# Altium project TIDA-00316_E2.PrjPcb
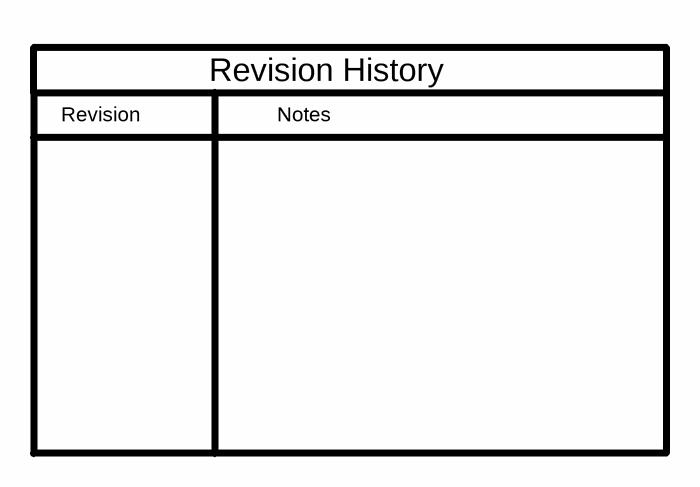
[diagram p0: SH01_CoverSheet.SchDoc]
CopyrightYear: 2015; EVM_Orderable: N/A; PCB_Layout: Avinash N; PCB_Rev: E2; PRJ_Customer: Public Release; PRJ_Engineer: Sanjay Pithadia; PRJ_Number: TIDA-00316; PRJ_Title: Motor Current Measurement using Hall Sensors; SCH_Rev: E2; TechSupport: http://www.ti.com/support; TID: ChangeMe!
6 sheets, 219 parts. Net scope: flat (ports and power ports of the same name join across sheets).
Board file: TIDA-00316_E2.PcbDoc
Sheets:
  SH01_CoverSheet.SchDoc
  SH02_Power_supply.SchDoc
  SH03_Single_ended_SC_to_ADC.SchDoc
  SH04_Fully_differential_ended_SC_to_ADC.SchDoc
  SH05_180_pin_connector_interface.SchDoc
  SH06_Hardware.SchDoc

## Sheet SH01_CoverSheet.SchDoc: Block Diagram
size 431 x 279 mm; Date: Not shown in title block; ApprovedBy: Not shown in title block; CheckedBy: Not shown in title block; Author: Not shown in title block; CompanyName: Not shown in title block; DrawnBy: Sanjay Pithadia; Engineer: Sanjay Pithadia; Organization: Not shown in title block; Address1: Not shown in title block; Address2: Not shown in title block; Address3: Not shown in title block; Address4: Not shown in title block; DocumentNumber: 1; Revision: Use project parameter SCH_Rev; SheetNumber: 1; SheetTotal: 6; PageSetup: Record=PageOptions|CenterHorizontal=True|CenterVertical=True|PrintScale=1.00|XCorrection=1.00|YCorrection=1.00|PrintKind=0|BorderSize=5000000|LeftOffset=0|BottomOffset=0|Orientation=2|PaperLength=1000|PaperWidth=1000|Scale=100|PaperSource=15|PrintQuality=600|MediaType=1|DitherType=10|PaperKind=Letter|PrintScaleMode=1

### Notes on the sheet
- Revision
- Notes
- Revision History

## Sheet SH02_Power_supply.SchDoc: Power Supply
size 431 x 279 mm; Date: Not shown in title block; ApprovedBy: Not shown in title block; CheckedBy: Not shown in title block; Author: Not shown in title block; CompanyName: Not shown in title block; DrawnBy: Sanjay Pithadia; Engineer: Sanjay Pithadia; Organization: Not shown in title block; Address1: Not shown in title block; Address2: Not shown in title block; Address3: Not shown in title block; Address4: Not shown in title block; DocumentNumber: 1; Revision: Use project parameter SCH_Rev; SheetNumber: 2; SheetTotal: 6; PageSetup: Record=PageOptions|CenterHorizontal=True|CenterVertical=True|PrintScale=1.00|XCorrection=1.00|YCorrection=1.00|PrintKind=0|BorderSize=5000000|LeftOffset=0|BottomOffset=0|Orientation=2|PaperLength=1000|PaperWidth=1000|Scale=100|PaperSource=15|PrintQuality=600|MediaType=1|DitherType=10|PaperKind=Letter|PrintScaleMode=1
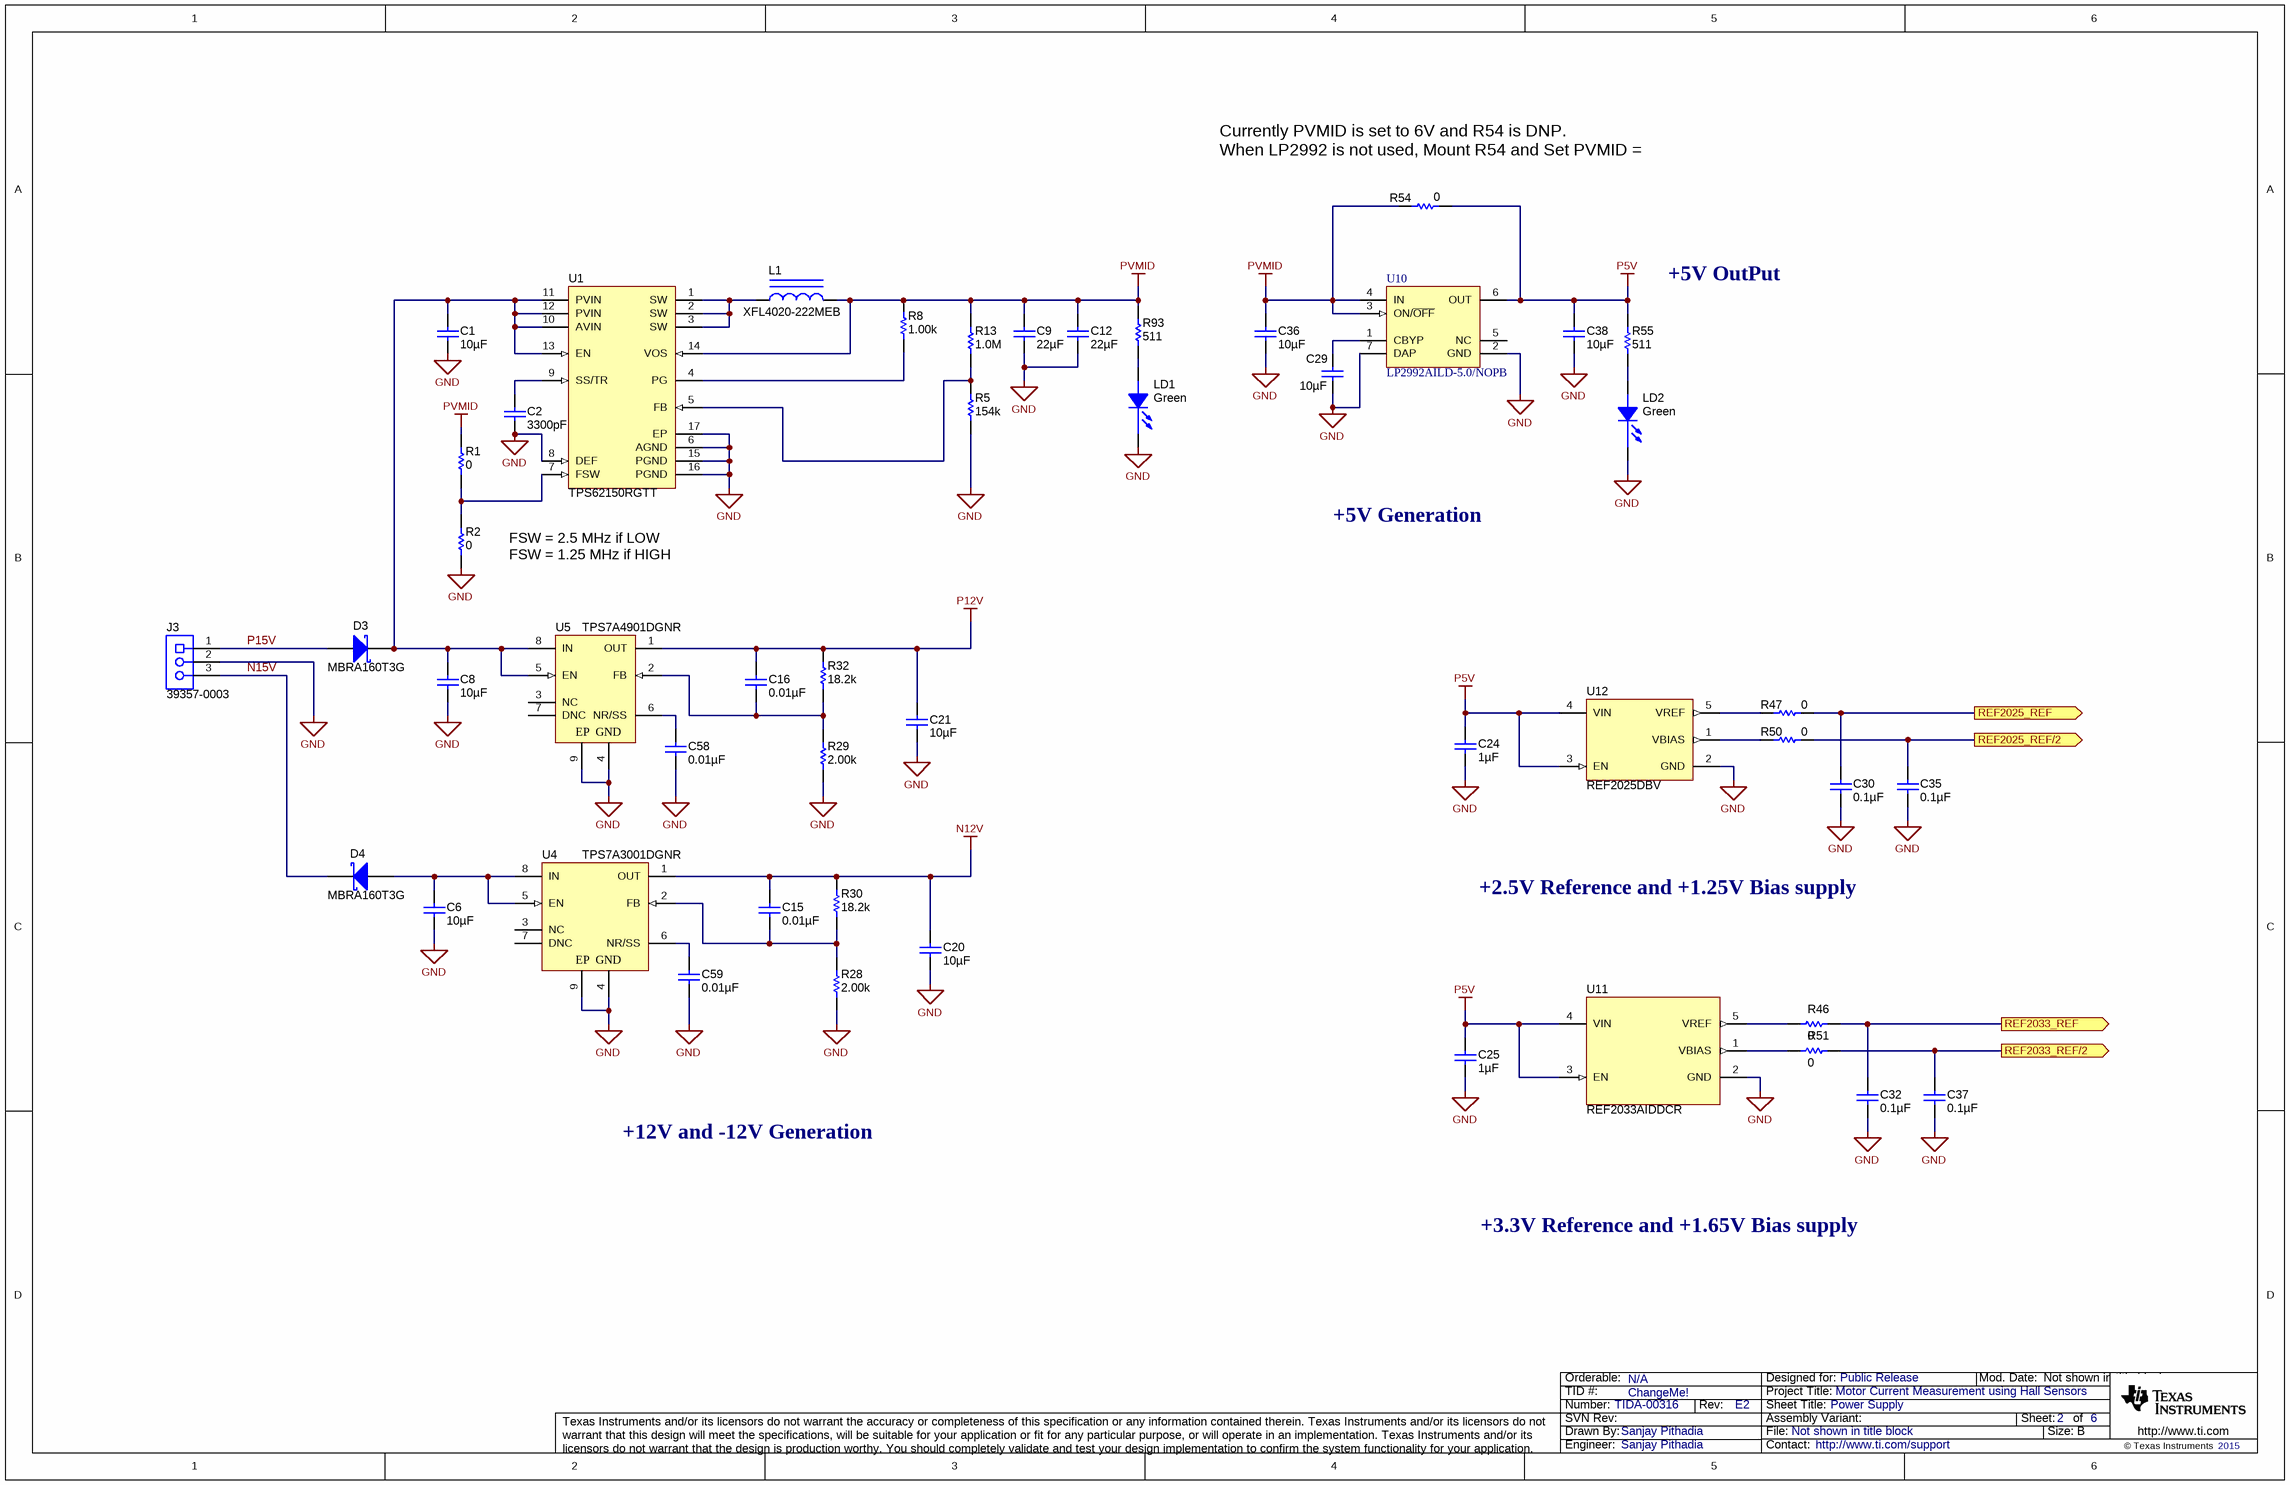
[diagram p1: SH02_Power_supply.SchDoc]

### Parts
C1  ValueDisplayed: 10µF  [1210]  (hidden comment: C3216X7R1V106M160AC)
C2  ValueDisplayed: 3300pF  [0805_HV]  (hidden comment: C0805C332K5RACTU)
C6  ValueDisplayed: 10µF  [0805_140]  (hidden comment: GRM21BR61E106KA73L)
C8  ValueDisplayed: 10µF  [0805_140]  (hidden comment: GRM21BR61E106KA73L)
C9  ValueDisplayed: 22µF  [0805_HV]  (hidden comment: C2012X5R1C226K125AC)
C12  ValueDisplayed: 22µF  [0805_HV]  (hidden comment: C2012X5R1C226K125AC)
C15  ValueDisplayed: 0.01µF  [0603]  (hidden comment: C1608C0G1E103J)
C16  ValueDisplayed: 0.01µF  [0603]  (hidden comment: C1608C0G1E103J)
C20  ValueDisplayed: 10µF  [0805_140]  (hidden comment: GRM21BR61E106KA73L)
C21  ValueDisplayed: 10µF  [0805_140]  (hidden comment: GRM21BR61E106KA73L)
C24  ValueDisplayed: 1µF  [0805_HV]  (hidden comment: C0805C105K8RACTU)
C25  ValueDisplayed: 1µF  [0805_HV]  (hidden comment: C0805C105K8RACTU)
C29  ValueDisplayed: 10µF  [0805_140]  (hidden comment: GRM21BR61E106KA73L)
C30  ValueDisplayed: 0.1µF  [0603]  (hidden comment: GRM188R71H104KA93D)
C32  ValueDisplayed: 0.1µF  [0603]  (hidden comment: GRM188R71H104KA93D)
C35  ValueDisplayed: 0.1µF  [0603]  (hidden comment: GRM188R71H104KA93D)
C36  ValueDisplayed: 10µF  [0805_140]  (hidden comment: GRM21BR61E106KA73L)
C37  ValueDisplayed: 0.1µF  [0603]  (hidden comment: GRM188R71H104KA93D)
C38  ValueDisplayed: 10µF  [0805_140]  (hidden comment: GRM21BR61E106KA73L)
C58  ValueDisplayed: 0.01µF  [0603]  (hidden comment: C1608C0G1E103J)
C59  ValueDisplayed: 0.01µF  [0603]  (hidden comment: C1608C0G1E103J)
D3  MBRA160T3G  [SMA]
D4  MBRA160T3G  [SMA]
J3  39357-0003  [Molex_39357-0003]
L1  XFL4020-222MEB  [XFL4020]
LD1  value Green  [LED0603AA]  (hidden comment: LED_LG L29K-G2J1-24-Z)
LD2  value Green  [LED0603AA]  (hidden comment: LED_LG L29K-G2J1-24-Z)
R1  ValueDisplayed: 0  [0603]  (hidden comment: CRCW06030000Z0EA)
R2  ValueDisplayed: 0  [0603]  (hidden comment: CRCW06030000Z0EA)
R5  ValueDisplayed: 154k  [0603]  (hidden comment: CRCW0603154KFKEA)
R8  ValueDisplayed: 1.00k  [0603]  (hidden comment: CRCW06031K00FKEA)
R13  ValueDisplayed: 1.0M  [0603]  (hidden comment: CRCW06031M00JNEA)
R28  ValueDisplayed: 2.00k  [0603]  (hidden comment: CRCW06032K00FKEA)
R29  ValueDisplayed: 2.00k  [0603]  (hidden comment: CRCW06032K00FKEA)
R30  ValueDisplayed: 18.2k  [0603]  (hidden comment: CRCW060318K2FKEA)
R32  ValueDisplayed: 18.2k  [0603]  (hidden comment: CRCW060318K2FKEA)
R46  value 0  [0603]  (hidden comment: CRCW06030000Z0EA)
R47  value 0  [0603]  (hidden comment: CRCW06030000Z0EA)
R50  value 0  [0603]  (hidden comment: CRCW06030000Z0EA)
R51  value 0  [0603]  (hidden comment: CRCW06030000Z0EA)
R54  value 0  [0603]  (hidden comment: CRCW06030000Z0EA)
R55  ValueDisplayed: 511  [0603]  (hidden comment: RT0603DRE07511RL)
R93  ValueDisplayed: 511  [0603]  (hidden comment: RT0603DRE07511RL)
U1  TPS62150RGTT  [RGT0016C]
U4  TPS7A3001DGNR  [DGN0008D_N]
U5  TPS7A4901DGNR  [DGN0008D_N]
U10  LP2992AILD-5.0/NOPB  [LDE06A]
U11  REF2033AIDDCR  [DDC0005A_N]
U12  REF2025DBV  [DBV0005A_N]

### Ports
REF2025_REF (out), REF2025_REF/2 (out), REF2033_REF (out), REF2033_REF/2 (out)

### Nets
GND: C1.2 C2.2 C6.2 C8.2 C9.2 C12.2 C20.2 C21.2 C24.2 C25.2 C29.2 C30.2 C32.2 C35.2 C36.2 C37.2 C38.2 C58.2 C59.2 J3.2 LD1.1(C) LD2.1(C) R2.1 R5.1 R28.1 R29.1 U1.6(AGND) U1.8(DEF) U1.15(PGND) U1.16(PGND) U1.17(EP) U4.4(GND) U4.9(EP) U5.4(GND) U5.9(EP) U10.2(GND) U10.7(DAP) U11.2(GND) U12.2(GND)
N12V: C15.1 C20.1 R30.2 U4.1(OUT)
P5V: C24.1 C25.1 C38.1 R54.1 R55.2 U10.6(OUT) U11.3(EN) U11.4(VIN) U12.3(EN) U12.4(VIN)
P12V: C16.1 C21.1 R32.2 U5.1(OUT)
PVMID: C9.1 C12.1 C36.1 L1.2 R1.2 R8.2 R13.2 R54.2 R93.2 U1.14(VOS) U10.3(ON/~{OFF}) U10.4(IN)
N15V: D4.1(K) J3.3
P15V: D3.2(A) J3.1
REF2025_REF: C30.1 R47.1 ; port REF2025_REF
REF2025_REF/2: C35.1 R50.1 ; port REF2025_REF/2
REF2033_REF: C32.1 R46.1 ; port REF2033_REF
REF2033_REF/2: C37.1 R51.1 ; port REF2033_REF/2
NetC1_1: C1.1 C8.1 D3.1(K) U1.10(AVIN) U1.11(PVIN) U1.12(PVIN) U1.13(EN) U5.5(EN) U5.8(IN)
NetC2_1: C2.1 U1.9(SS/TR)
NetC6_1: C6.1 D4.2(A) U4.5(EN) U4.8(IN)
NetC15_2: C15.2 R28.2 R30.1 U4.2(FB)
NetC16_2: C16.2 R29.2 R32.1 U5.2(FB)
NetC29_1: C29.1 U10.1(CBYP)
NetC58_1: C58.1 U5.6(NR/SS)
NetC59_1: C59.1 U4.6(NR/SS)
NetL1_1: L1.1 U1.1(SW) U1.2(SW) U1.3(SW)
NetLD1_2: LD1.2(A) R93.1
NetLD2_2: LD2.2(A) R55.1
NetR1_1: R1.1 R2.2 U1.7(FSW)
NetR5_2: R5.2 R13.1 U1.5(FB)
NetR8_1: R8.1 U1.4(PG)
NetR46_2: R46.2 U11.5(VREF)
NetR47_2: R47.2 U12.5(VREF)
NetR50_2: R50.2 U12.1(VBIAS)
NetR51_2: R51.2 U11.1(VBIAS)

Not connected (* = marked no-connect by the designer): U4 3(NC) 7(DNC); U5 3(NC) 7(DNC); U10 5(NC)

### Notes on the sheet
- (near R54) Currently PVMID is set to 6V and R54 is DNP.
  When LP2992 is not used, Mount R54 and Set PVMID = 5V
- +5V OutPut
- FSW = 2.5 MHz if LOW
  FSW = 1.25 MHz if HIGH
- +5V Generation
- +2.5V Reference and +1.25V Bias supply
- +12V and -12V Generation
- +3.3V Reference and +1.65V Bias supply

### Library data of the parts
C1 = C3216X7R1V106M160AC: CAP, CERM, 10 µF, 35 V, +/- 20%, X7R, 1206_190; Manufacturer: TDK; Polarized: N; CompType: Capacitor; Value: 10uF; U/M: EA; Cap_F: 0.00001; Tolerance_%: 20; Value1: Unknown; VDC_V: 35; Value2: 35V; TaMin_C: -55; TaMax_C: 125; Cap_Case: 1206
C2 = C0805C332K5RACTU: CAP, CERM, 3300 pF, 50 V, +/- 10%, X7R, 0805; Manufacturer: Kemet; Polarized: N; CompType: Capacitor; Value: 3300pF; U/M: EA; Cap_F: 0.0000000033; Tolerance_%: 10; ESR_ohm: 0.332; Value1: 0.332 ohm; VDC_V: 50; Value2: 50V; IRMS_A: 0.319; TaMin_C: -55; TaMax_C: 125; Cap_Case: 0805
C6 C8 C20 C21 C29 C36 C38 = GRM21BR61E106KA73L: CAP, CERM, 10 µF, 25 V, +/- 10%, X5R, 0805_140; Manufacturer: MuRata; Polarized: N; CompType: Capacitor; Value: 10uF; U/M: EA; Cap_F: 0.00001; Tolerance_%: 10; Value1: Unknown; VDC_V: 25; Value2: 25V; TaMin_C: -55; TaMax_C: 85; Cap_Case: 0805
C9 C12 = C2012X5R1C226K125AC: CAP, CERM, 22 µF, 16 V, +/- 10%, X5R, 0805; Manufacturer: TDK; Polarized: N; CompType: Capacitor; Value: 22uF; U/M: EA; Cap_F: 0.000022; Tolerance_%: 10; Value1: Unknown; VDC_V: 16; Value2: 16V; TaMin_C: -55; TaMax_C: 85; Cap_Case: 0805
C15 C16 C58 C59 = C1608C0G1E103J: CAP, CERM, 0.01 µF, 25 V, +/- 5%, C0G/NP0, 0603; Manufacturer: TDK; Polarized: N; CompType: Capacitor; Value: 0.01uF; U/M: EA; Cap_F: 0.00000001; Tolerance_%: 5; Value1: Unknown; VDC_V: 25; Value2: 25V; TaMin_C: -55; TaMax_C: 125
C24 C25 = C0805C105K8RACTU: CAP, CERM, 1uF, 10V, +/-10%, X7R, 0805; Manufacturer: Kemet; Polarized: N; CompType: Capacitor; U/M: EA; Cap_F: 0.000001; Tolerance_%: 10; ESR_Ohm: 0.015; Value1: 0.015 ohm; IRMS_A: 8.19; TaMin_C: -55; TaMax_C: 125; Cap_Case: 0805
C30 C32 C35 C37 = GRM188R71H104KA93D: CAP, CERM, 0.1 µF, 50 V, +/- 10%, X7R, 0603; Manufacturer: MuRata; Polarized: N; CompType: Capacitor; Value: 0.1uF; U/M: EA; Cap_F: 0.0000001; Tolerance_%: 10; Value1: Unknown; VDC_V: 50; Value2: 50V; TaMin_C: -55; TaMax_C: 125
D3 D4 = MBRA160T3G: Diode, Schottky, 60V, 1A, SMA; Manufacturer: ON Semiconductor; U/M: EA; Vf_V: 0.51; Value2: 0.51V; Io_A: 1; Vr_V: 60; TJmax_C: 150; RJC_CperW: 35
J3 = 39357-0003: Terminal Block, 3.5 mm, 3x1, Tin, TH; Manufacturer: Molex; SymbolCreator: a0412235; U/M: EA
L1 = XFL4020-222MEB: Inductor, Shielded, Composite, 2.2 µH, 3.7 A, 0.02 ohm, SMD; Manufacturer: Coilcraft; Value: 2.2uH; Ind_H: 2.2E-6; ValueDisplayed: 2.2µH; Imax_A: 3.7; Irms: 8A @ 40C rise; Isat: 3.7A @ 30% inductance drop; DCR_ohm: 0.02; Value2: 3.7A
LD1 LD2 = LED_LG L29K-G2J1-24-Z: LED SmartLED Green 570NM; Manufacturer: OSRAM; SymbolCreator: x0120606
R1 R2 = CRCW06030000Z0EA: RES, 0, 5%, 0.1 W, 0603; Manufacturer: Vishay-Dale; CompType: Resistor; Value: 0; Value_Code: 0000; Tolerance_%: 5; Power_W: 0.1; Value2: 0.1W; VDC_V: 75; TempCo: 200 ppm/C; EIA_Code: E24; U/M: EA
R5 = CRCW0603154KFKEA: RES, 154 k, 1%, 0.1 W, 0603; Manufacturer: Vishay-Dale; CompType: Resistor; Value: 154k; Res_ohm: 154000; Tolerance_%: 1; Power_W: 0.1; Value2: 0.1W; VDC_V: 75; TempCo: 100 ppm/C; EIA_Code: E96; U/M: EA
R8 = CRCW06031K00FKEA: RES, 1.00 k, 1%, 0.1 W, 0603; Manufacturer: Vishay-Dale; CompType: Resistor; Value: 1.00k; Res_ohm: 1000; Value_Code: 1k00; Tolerance_%: 1; Power_W: 0.1; Value2: 0.1W; VDC_V: 75; TempCo: 100 ppm/C; EIA_Code: E96; U/M: EA
R13 = CRCW06031M00JNEA: RES, 1.0 M, 5%, 0.1 W, 0603; Manufacturer: Vishay-Dale; CompType: Resistor; Value: 1.0Meg; Res_ohm: 1000000; Value_Code: 1M00; Tolerance_%: 5; Power_W: 0.1; Value2: 0.1W; VDC_V: 75; TempCo: 200 ppm/C; EIA_Code: E24; U/M: EA
R28 R29 = CRCW06032K00FKEA: RES, 2.00 k, 1%, 0.1 W, 0603; Manufacturer: Vishay-Dale; CompType: Resistor; Value: 2.00k; Res_ohm: 2000; Value_Code: 2k00; Tolerance_%: 1; Power_W: 0.1; Value2: 0.1W; VDC_V: 75; TempCo: 100 ppm/C; EIA_Code: E96; U/M: EA
R30 R32 = CRCW060318K2FKEA: RES, 18.2 k, 1%, 0.1 W, 0603; Manufacturer: Vishay-Dale; CompType: Resistor; Value: 18.2k; Res_ohm: 18200; Value_Code: 18k2; Tolerance_%: 1; Power_W: 0.1; Value2: 0.1W; VDC_V: 75; TempCo: 100 ppm/C; EIA_Code: E96; U/M: EA
R46 R47 R50 R51 R54 = CRCW06030000Z0EA: RES, 0 ohm, 5%, 0.1W, 0603; Manufacturer: Vishay-Dale; CompType: Resistor; Value_Code: 0000; Tolerance_%: 5; Power_W: 0.1; VDC_V: 75; TempCo: 200 ppm/C; EIA_Code: E24; U/M: EA
R55 R93 = RT0603DRE07511RL: RES, 511, 0.5%, 0.1 W, 0603; Manufacturer: Yageo America; CompType: Resistor; Value: 511; Value_Code: 511R; Tolerance_%: 0.5; Power_W: 0.1; Value2: 0.1W; VDC_V: 75; TempCo: 50 ppm/C; EIA_Code: E192; U/M: EA
U1 = TPS62150RGTT: Buck Step Down Regulator with 3 to 17 V Input and 0.9 to 6 V Output, -40 to 85 degC, 16-Pin QFN (RGT), Green (RoHS & no Sb/Br); Manufacturer: Texas Instruments; Alternate Manufacturer: None; Alternate PartNumber: Equivalent; Duty Cycle(Max)(%): 100; Iout(Max)(A): 1; Iq(Typ)(mA): 0.017; Rating: Catalog; SubFamily: Step-Down Regulator; Switch Current Limit(Typ)(A): 1.7; Synchronous Rectification: TRUE; Vin(Max)(V): 17; Vin(Min)(V): 3; Vout(Max)(V): 6; Vout(Min)(V): 0.9
U4 = TPS7A3001DGNR: Single Output High PSRR LDO, 200 mA, Adjustable -1.18 to -33 V Output, -3 to -36 V Input, with Ultra-Low Noise, 8-pin MSOP (DGN), -40 to 125 degC, Green (RoHS & no Sb/Br); Manufacturer: Texas Instruments; Alternate Manufacturer: None; Alternate PartNumber: Equivalent; Accuracy(%): 1.5; Iout(Max)(A): 0.2; Iq(Typ)(mA): 0.05; SubFamily: Single Channel LDO; Vdo(Typ)(mV): 216
U5 = TPS7A4901DGNR: Single Output High PSRR LDO, 150 mA, Adjustable 1.2 to 33 V Output, 3 to 36 V Input, with Ultra-Low Noise, 8-pin MSOP (DGN), -40 to 125 degC, Green (RoHS & no Sb/Br); Manufacturer: Texas Instruments; Alternate Manufacturer: None; Alternate PartNumber: Equivalent; Accuracy(%): 1.5; Iout(Max)(A): 0.15; Iq(Typ)(mA): 0.06; Power Good: TRUE; SubFamily: Single Channel LDO; Vdo(Typ)(mV): 260; Vin(Max)(V): 36; Vin(Min)(V): 3; Vout Adj(Max)(V): 33; Vout Adj(Min)(V): 1.2
U10 = LP2992AILD-5.0/NOPB: Micropower 250 mA Low-Noise Ultra Low-Dropout Regulator, 6-pin LLP, Pb-Free; Manufacturer: Texas Instruments; PackageTopMarking: ZXYTT*L015A; PowerWise: N; CompType: LDO IC
U11 = REF2033AIDDCR: Low-Drift, Low-Power, Dual-Output, VREF and VREF / 2 Voltage References, DDC0005A; Alternate PartNumber: REF2033AIDDCT; Manufacturer: Texas Instruments; SymbolCreator: a0799628; CompType: IC; U/M: EA
U12 = REF2025DBV: DUAL OUTPUT VOLTAGE REFERENCE 2.5V, DBV0005A; Alternate Manufacturer: None; Manufacturer: Texas Instruments; SymbolCreator: a0799628; CompType: IC; U/M: EA

## Sheet SH03_Single_ended_SC_to_ADC.SchDoc: Signal Chain - Pseudo Differential
size 431 x 279 mm; Date: Not shown in title block; ApprovedBy: Not shown in title block; CheckedBy: Not shown in title block; Author: Not shown in title block; CompanyName: Not shown in title block; DrawnBy: Sanjay Pithadia; Engineer: Sanjay Pithadia; Organization: Not shown in title block; Address1: Not shown in title block; Address2: Not shown in title block; Address3: Not shown in title block; Address4: Not shown in title block; DocumentNumber: 1; Revision: Use project parameter SCH_Rev; SheetNumber: 3; SheetTotal: 6; PageSetup: Record=PageOptions|CenterHorizontal=True|CenterVertical=True|PrintScale=1.00|XCorrection=1.00|YCorrection=1.00|PrintKind=0|BorderSize=5000000|LeftOffset=0|BottomOffset=0|Orientation=2|PaperLength=1000|PaperWidth=1000|Scale=100|PaperSource=15|PrintQuality=600|MediaType=1|DitherType=10|PaperKind=Letter|PrintScaleMode=1
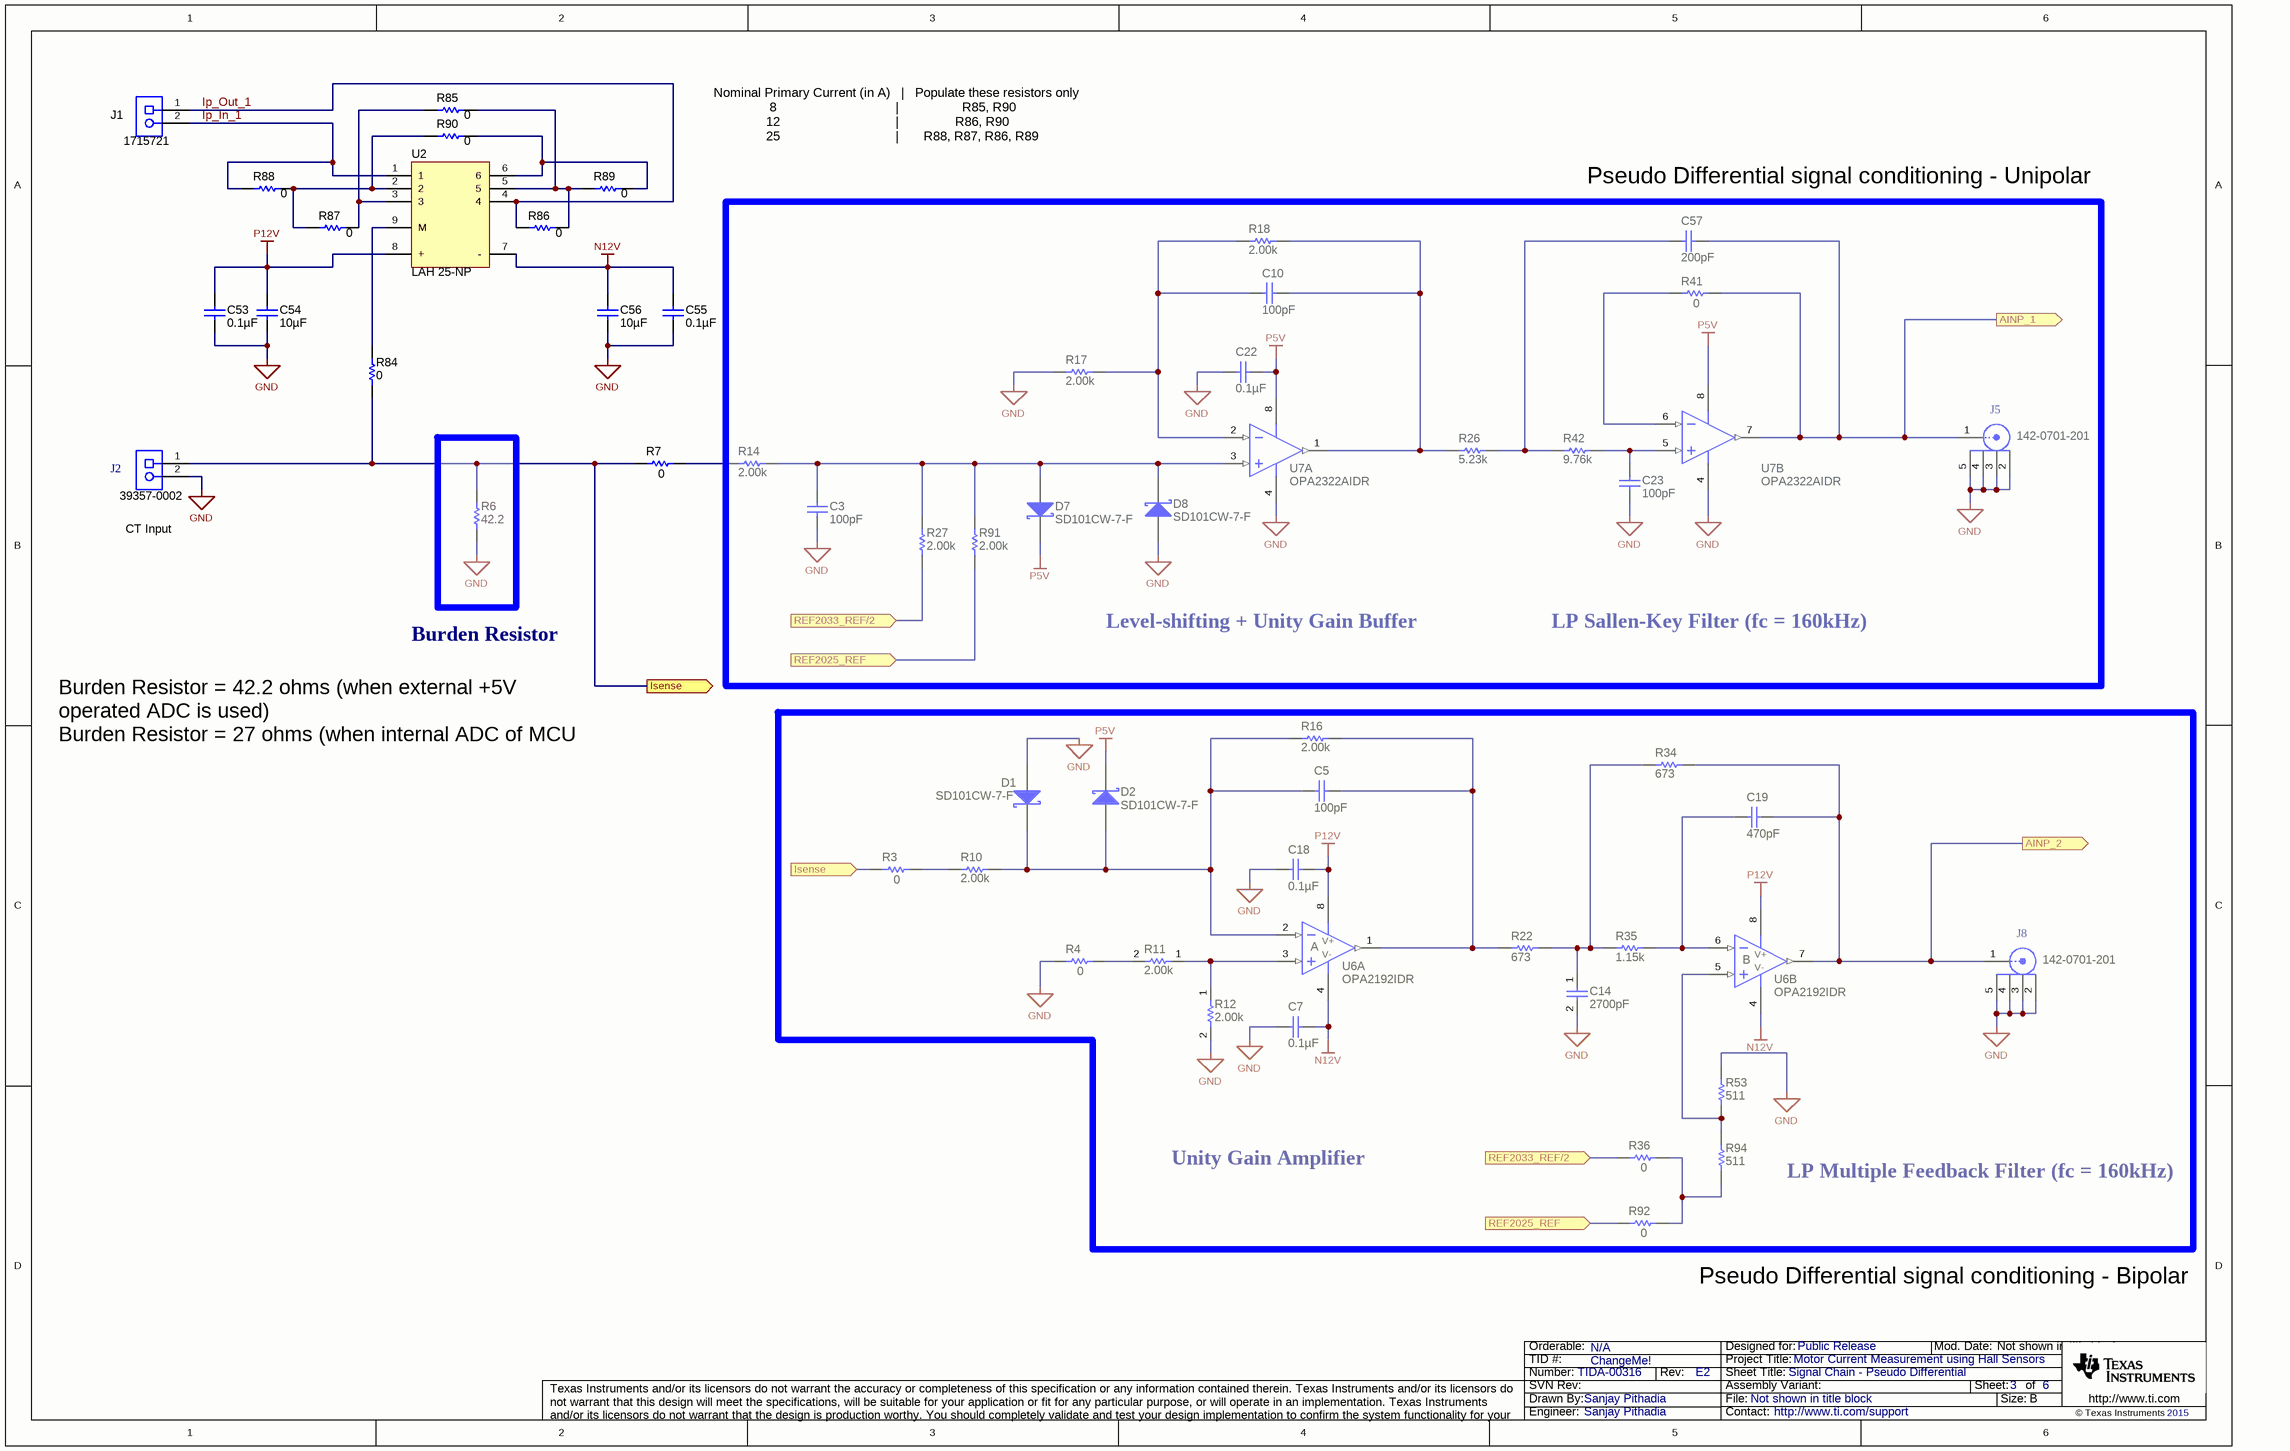
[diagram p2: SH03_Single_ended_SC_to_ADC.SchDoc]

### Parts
C3  ValueDisplayed: 100pF  [0603]  (hidden comment: C1608C0G2A101J)
C5  ValueDisplayed: 100pF  [0603]  (hidden comment: C1608C0G2A101J)
C7  ValueDisplayed: 0.1µF  [0603]  (hidden comment: GRM188R71H104KA93D)
C10  ValueDisplayed: 100pF  [0603]  (hidden comment: C1608C0G2A101J)
C14  ValueDisplayed: 2700pF  [0603]  (hidden comment: C1608C0G1H272J)
C18  ValueDisplayed: 0.1µF  [0603]  (hidden comment: GRM188R71H104KA93D)
C19  ValueDisplayed: 470pF  [0603]  (hidden comment: 06035A471JAT2A)
C22  ValueDisplayed: 0.1µF  [0603]  (hidden comment: GRM188R71H104KA93D)
C23  ValueDisplayed: 100pF  [0603]  (hidden comment: C1608C0G2A101J)
C53  ValueDisplayed: 0.1µF  [0603]  (hidden comment: GRM188R71H104KA93D)
C54  ValueDisplayed: 10µF  [0805_140]  (hidden comment: GRM21BR61E106KA73L)
C55  ValueDisplayed: 0.1µF  [0603]  (hidden comment: GRM188R71H104KA93D)
C56  ValueDisplayed: 10µF  [0805_140]  (hidden comment: GRM21BR61E106KA73L)
C57  ValueDisplayed: 200pF  [0603]  (hidden comment: GRM1885C2A201JA01D)
D1  SD101CW-7-F  [SOD-123]
D2  SD101CW-7-F  [SOD-123]
D7  SD101CW-7-F  [SOD-123]
D8  SD101CW-7-F  [SOD-123]
J1  1715721  [PhoenixContact_1715721]
J2  39357-0002  [Molex_39357-0002]
J5  142-0701-201  [Johnson_142-0701-20x]
J8  142-0701-201  [Johnson_142-0701-20x]
R3  value 0  [0603]  (hidden comment: CRCW06030000Z0EA)
R4  value 0  [0603]  (hidden comment: CRCW06030000Z0EA)
R6  ValueDisplayed: 42.2  [0805_HV]  (hidden comment: CRCW080542R2FKEA)
R7  value 0  [0603]  (hidden comment: CRCW06030000Z0EA)
R10  ValueDisplayed: 2.00k  [0603]  (hidden comment: RC0603FR-072KL)
R11  ValueDisplayed: 2.00k  [0603]  (hidden comment: RC0603FR-072KL)
R12  ValueDisplayed: 2.00k  [0603]  (hidden comment: RC0603FR-072KL)
R14  ValueDisplayed: 2.00k  [0603]  (hidden comment: RC0603FR-072KL)
R16  ValueDisplayed: 2.00k  [0603]  (hidden comment: RC0603FR-072KL)
R17  ValueDisplayed: 2.00k  [0603]  (hidden comment: RC0603FR-072KL)
R18  ValueDisplayed: 2.00k  [0603]  (hidden comment: RC0603FR-072KL)
R22  ValueDisplayed: 673  [0603]  (hidden comment: RT0603BRD07673RL)
R26  ValueDisplayed: 5.23k  [0603]  (hidden comment: CRCW06035K23FKEA)
R27  ValueDisplayed: 2.00k  [0603]  (hidden comment: RC0603FR-072KL)
R34  ValueDisplayed: 673  [0603]  (hidden comment: RT0603BRD07673RL)
R35  ValueDisplayed: 1.15k  [0603]  (hidden comment: CRCW06031K15FKEA)
R36  value 0  [0603]  (hidden comment: CRCW06030000Z0EA)
R41  value 0  [0603]  (hidden comment: CRCW06030000Z0EA)
R42  ValueDisplayed: 9.76k  [0603]  (hidden comment: CRCW06039K76FKEA)
R53  ValueDisplayed: 511  [0603]  (hidden comment: RT0603DRE07511RL)
R84  value 0  [0603]  (hidden comment: CRCW06030000Z0EA)
R85  ValueDisplayed: 0  [1206]  (hidden comment: RC1206JR-070RL)
R86  ValueDisplayed: 0  [1206]  (hidden comment: RC1206JR-070RL)
R87  ValueDisplayed: 0  [1206]  (hidden comment: RC1206JR-070RL)
R88  ValueDisplayed: 0  [1206]  (hidden comment: RC1206JR-070RL)
R89  ValueDisplayed: 0  [1206]  (hidden comment: RC1206JR-070RL)
R90  ValueDisplayed: 0  [1206]  (hidden comment: RC1206JR-070RL)
R91  ValueDisplayed: 2.00k  [0603]  (hidden comment: RC0603FR-072KL)
R92  value 0  [0603]  (hidden comment: CRCW06030000Z0EA)
R94  ValueDisplayed: 511  [0603]  (hidden comment: RT0603DRE07511RL)
U2  LAH 25-NP  [LAH25-NP]
U6  OPA2192IDR  [D0008A_N]  (parts A,B of 2)
U7  OPA2322AIDR  [D0008A_N]  (parts A,B of 2)

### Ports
AINP_1 (out), AINP_2 (out), Isense (in), Isense (out), REF2025_REF (in), REF2033_REF/2 (in)

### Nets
GND: C3.2 C7.2 C14.2 C18.2 C22.2 C23.2 C53.2 C54.2 C55.2 C56.2 D1.2(A) D8.2(A) J2.2 J5.2 J5.3 J5.4 J5.5 J8.2 J8.3 J8.4 J8.5 R4.2 R6.1 R12.2 R17.1 R53.2 U7.4(V-)
N12V: C7.1 C55.1 C56.1 U2.7(-) U6.4(V-)
P5V: C22.1 D2.1(K) D7.1(K) U7.8(V+)
P12V: C18.1 C53.1 C54.1 U2.8(+) U6.8(V+)
AINP_1: C57.1 J5.1 R41.1 U7.7(OUT_B) ; port AINP_1
AINP_2: C19.1 J8.1 R34.2 U6.7(OUT) ; port AINP_2
Ip_In_1: J1.2 R88.1 U2.1
Ip_Out_1: J1.1 R86.1 U2.4
Isense: J2.1 R3.2 R6.2 R7.2 R84.2 ; port Isense
REF2025_REF: R91.1 R92.2 ; port REF2025_REF
REF2033_REF/2: R27.1 R36.2 ; port REF2033_REF/2
NetC3_1: C3.1 D7.2(A) D8.1(K) R14.2 R27.2 R91.2 U7.3(IN_A+)
NetC5_1: C5.1 R16.1 R22.1 U6.1(OUT)
NetC5_2: C5.2 D1.1(K) D2.2(A) R10.2 R16.2 U6.2(IN-)
NetC10_1: C10.1 R18.1 R26.1 U7.1(OUT_A)
NetC10_2: C10.2 R17.2 R18.2 U7.2(IN_A-)
NetC14_1: C14.1 R22.2 R34.1 R35.1
NetC19_2: C19.2 R35.2 U6.6(IN-)
NetC23_1: C23.1 R42.2 U7.5(IN_B+)
NetC57_2: C57.2 R26.2 R42.1
NetR3_1: R3.1 R10.1
NetR4_1: R4.1 R11.2
NetR7_1: R7.1 R14.1
NetR11_1: R11.1 R12.1 U6.3(IN+)
NetR36_1: R36.1 R92.1 R94.1
NetR41_2: R41.2 U7.6(IN_B-)
NetR53_1: R53.1 R94.2 U6.5(IN+)
NetR84_1: R84.1 U2.9(M)
NetR85_1: R85.1 R87.2 U2.3
NetR85_2: R85.2 R86.2 R89.1 U2.5
NetR87_1: R87.1 R88.2 R90.1 U2.2
NetR89_2: R89.2 R90.2 U2.6

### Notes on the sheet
- Nominal Primary Current (in A)   |   Populate these resistors only
  8                                  |                  R85, R90
  12                                 |                R86, R90
  25                                 |       R88, R87, R86, R89
- Pseudo Differential signal conditioning - Unipolar
- (near J2) CT Input
- Burden Resistor
- Level-shifting + Unity Gain Buffer
- LP Sallen-Key Filter (fc = 160kHz)
- Burden Resistor = 42.2 ohms (when external +5V operated ADC is used)
  Burden Resistor = 27 ohms (when internal ADC of MCU is used)
- Unity Gain Amplifier
- LP Multiple Feedback Filter (fc = 160kHz)
- (near R92) Pseudo Differential signal conditioning - Bipolar

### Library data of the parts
C3 C5 C10 C23 = C1608C0G2A101J: CAP, CERM, 100 pF, 100 V, +/- 5%, C0G/NP0, 0603; Manufacturer: TDK; Polarized: N; CompType: Capacitor; Value: 100pF; U/M: EA; Cap_F: 0.0000000001; Tolerance_%: 5; ESR_ohm: 0.1202; Value1: 0.1202 ohm; VDC_V: 100; Value2: 100V; TaMin_C: -55; TaMax_C: 125
C7 C18 C22 C53 C55 = GRM188R71H104KA93D: as C30 on sheet SH02_Power_supply
C14 = C1608C0G1H272J: CAP, CERM, 2700 pF, 50 V, +/- 5%, C0G/NP0, 0603; Manufacturer: TDK; Polarized: N; CompType: Capacitor; Value: 2700pF; U/M: EA; Cap_F: 0.0000000027; Tolerance_%: 5; Value1: Unknown; VDC_V: 50; Value2: 50V; TaMin_C: -55; TaMax_C: 125
C19 = 06035A471JAT2A: CAP, CERM, 470 pF, 50 V, +/- 5%, C0G/NP0, 0603; Manufacturer: AVX; Polarized: N; CompType: Capacitor; Value: 470pF; U/M: EA; Cap_F: 0.00000000047; Tolerance_%: 5; ESR_ohm: 0.063; Value1: 0.063 ohm; VDC_V: 50; Value2: 50V; TaMin_C: -55; TaMax_C: 125
C54 C56 = GRM21BR61E106KA73L: as C6 on sheet SH02_Power_supply
C57 = GRM1885C2A201JA01D: CAP, CERM, 200 pF, 100 V, +/- 5%, C0G/NP0, 0603; Manufacturer: MuRata; Polarized: N; CompType: Capacitor; Value: 200pF; U/M: EA; Cap_F: 0.0000000002; Tolerance_%: 5; Value1: Unknown; VDC_V: 100; Value2: 100V; TaMin_C: -55; TaMax_C: 125
D1 D2 D7 D8 = SD101CW-7-F: Diode, Schottky, 40 V, 0.015 A, SOD-123; Manufacturer: Diodes Inc.; U/M: EA; Vf_V: 0.8; Value: 40V; Value1: 0.015A; Value2: 0.8V; Io_A: 0.015; Vr_V: 40
J1 = 1715721: Conn Term Block, 2POS, 5.08mm, TH; Manufacturer: Phoenix Contact; SymbolCreator: a0412235; CompType: Terminal Block; U/M: EA; Value: 2x1
J2 = 39357-0002: Terminal Block, 3.5 mm, 2x1, Tin, TH; Manufacturer: Molex; SymbolCreator: a0412235; U/M: EA
J5 J8 = 142-0701-201: Connector, TH, SMA; Manufacturer: Emerson Network Power; SymbolCreator: X0208326; U/M: EA
R3 R4 R7 R36 R41 R84 R92 = CRCW06030000Z0EA: as R46 on sheet SH02_Power_supply
R6 = CRCW080542R2FKEA: RES, 42.2, 1%, 0.125 W, 0805; Manufacturer: Vishay-Dale; CompType: Resistor; Value: 42.2; Value_Code: 42R2; Tolerance_%: 1; Power_W: 0.125; Value2: 0.125W; VDC_V: 150; TempCo: 100 ppm/C; EIA_Code: E96; U/M: EA
R10-R12 R14 R16-R18 R27 R91 = RC0603FR-072KL: RES, 2.00 k, 1%, 0.1 W, 0603; Manufacturer: Yageo America; CompType: Resistor; Value: 2.00k; Res_ohm: 2000; Value_Code: 2k00; Tolerance_%: 1; Power_W: 0.1; Value2: 0.1W; VDC_V: 150; TempCo: 200 ppm/C; EIA_Code: E96; U/M: EA
R22 R34 = RT0603BRD07673RL: RES, 673, 0.1%, 0.1 W, 0603; Manufacturer: Yageo America; CompType: Resistor; Value: 673; Value_Code: 673R; Tolerance_%: 0.1; Value2: 0.1W; VDC_V: 75; TempCo: 25 ppm/C; EIA_Code: E192; U/M: EA
R26 = CRCW06035K23FKEA: RES, 5.23 k, 1%, 0.1 W, 0603; Manufacturer: Vishay-Dale; CompType: Resistor; Value: 5.23k; Res_ohm: 5230; Value_Code: 5k23; Tolerance_%: 1; Power_W: 0.1; Value2: 0.1W; VDC_V: 75; TempCo: 100 ppm/C; EIA_Code: E96; U/M: EA
R35 = CRCW06031K15FKEA: RES, 1.15 k, 1%, 0.1 W, 0603; Manufacturer: Vishay-Dale; CompType: Resistor; Value: 1.15k; Res_ohm: 1150; Value_Code: 1k15; Tolerance_%: 1; Power_W: 0.1; Value2: 0.1W; VDC_V: 75; TempCo: 100 ppm/C; EIA_Code: E96; U/M: EA
R42 = CRCW06039K76FKEA: RES, 9.76 k, 1%, 0.1 W, 0603; Manufacturer: Vishay-Dale; CompType: Resistor; Value: 9.76k; Res_ohm: 9760; Value_Code: 9k76; Tolerance_%: 1; Power_W: 0.1; Value2: 0.1W; VDC_V: 75; TempCo: 100 ppm/C; EIA_Code: E96; U/M: EA
R53 R94 = RT0603DRE07511RL: as R55 on sheet SH02_Power_supply
R85-R90 = RC1206JR-070RL: RES, 0, 5%, 0.25 W, 1206; Manufacturer: Yageo America; CompType: Resistor; Value: 0; Value_Code: 0000; Tolerance_%: 5; Power_W: 0.25; Value2: 0.25W; VDC_V: 200; TempCo: 200 ppm/C; EIA_Code: E24; U/M: EA
U2 = LAH 25-NP: Current Transducer, 25A, TH; Manufacturer: LEM; SymbolCreator: Altium
U6 = OPA2192IDR: High Voltage, Rail-to-Rail Input/Output, Precision Operational Amplifiers, e-trim™ Series, D0008A; Manufacturer: Texas Instruments; CompType: IC; U/M: EA
U7 = OPA2322AIDR: 20 MHz, Low Noise, RRIO, CMOS Operational Amplifier, 1.8 to 5.5 V, -40 to 125 degC, 8-pin SOIC (D0008A), Green (RoHS & no Sb/Br); Manufacturer: Texas Instruments; Alternate Manufacturer: None; Alternate PartNumber: Equivalent; CMRR(Min)(dB): 90; GBW(Typ)(MHz): 20; IIB(Max)(pA): 10; Iq per channel(Max)(mA): 1.75; Number of Channels: 2; Offset Drift(Typ)(uV/C): 1.8; Packing: LARGE T&R; Rating: Catalog; Sub Family: High Output Current Amplifier (>=50mA), Low Input Bias Current Amp (<=10pA), Low Noise Amp (<=10nV/rtHz), Low Supply Voltage Amplifier (<=2.7V), Precision Amplifier; Total Supply Voltage(Max)(+5V is 5, +/-5V is 10): 5.5

## Sheet SH04_Fully_differential_ended_SC_to_ADC.SchDoc: Signal Chain - Fully Differential + ADS7854
size 431 x 279 mm; Date: Not shown in title block; ApprovedBy: Not shown in title block; CheckedBy: Not shown in title block; Author: Not shown in title block; CompanyName: Not shown in title block; DrawnBy: Sanjay Pithadia; Engineer: Sanjay Pithadia; Organization: Not shown in title block; Address1: Not shown in title block; Address2: Not shown in title block; Address3: Not shown in title block; Address4: Not shown in title block; DocumentNumber: 1; Revision: Use project parameter SCH_Rev; SheetNumber: 4; SheetTotal: 6; PageSetup: Record=PageOptions|CenterHorizontal=True|CenterVertical=True|PrintScale=1.00|XCorrection=1.00|YCorrection=1.00|PrintKind=0|BorderSize=5000000|LeftOffset=0|BottomOffset=0|Orientation=2|PaperLength=1000|PaperWidth=1000|Scale=100|PaperSource=15|PrintQuality=600|MediaType=1|DitherType=10|PrintScaleMode=1|PaperKind=Letter
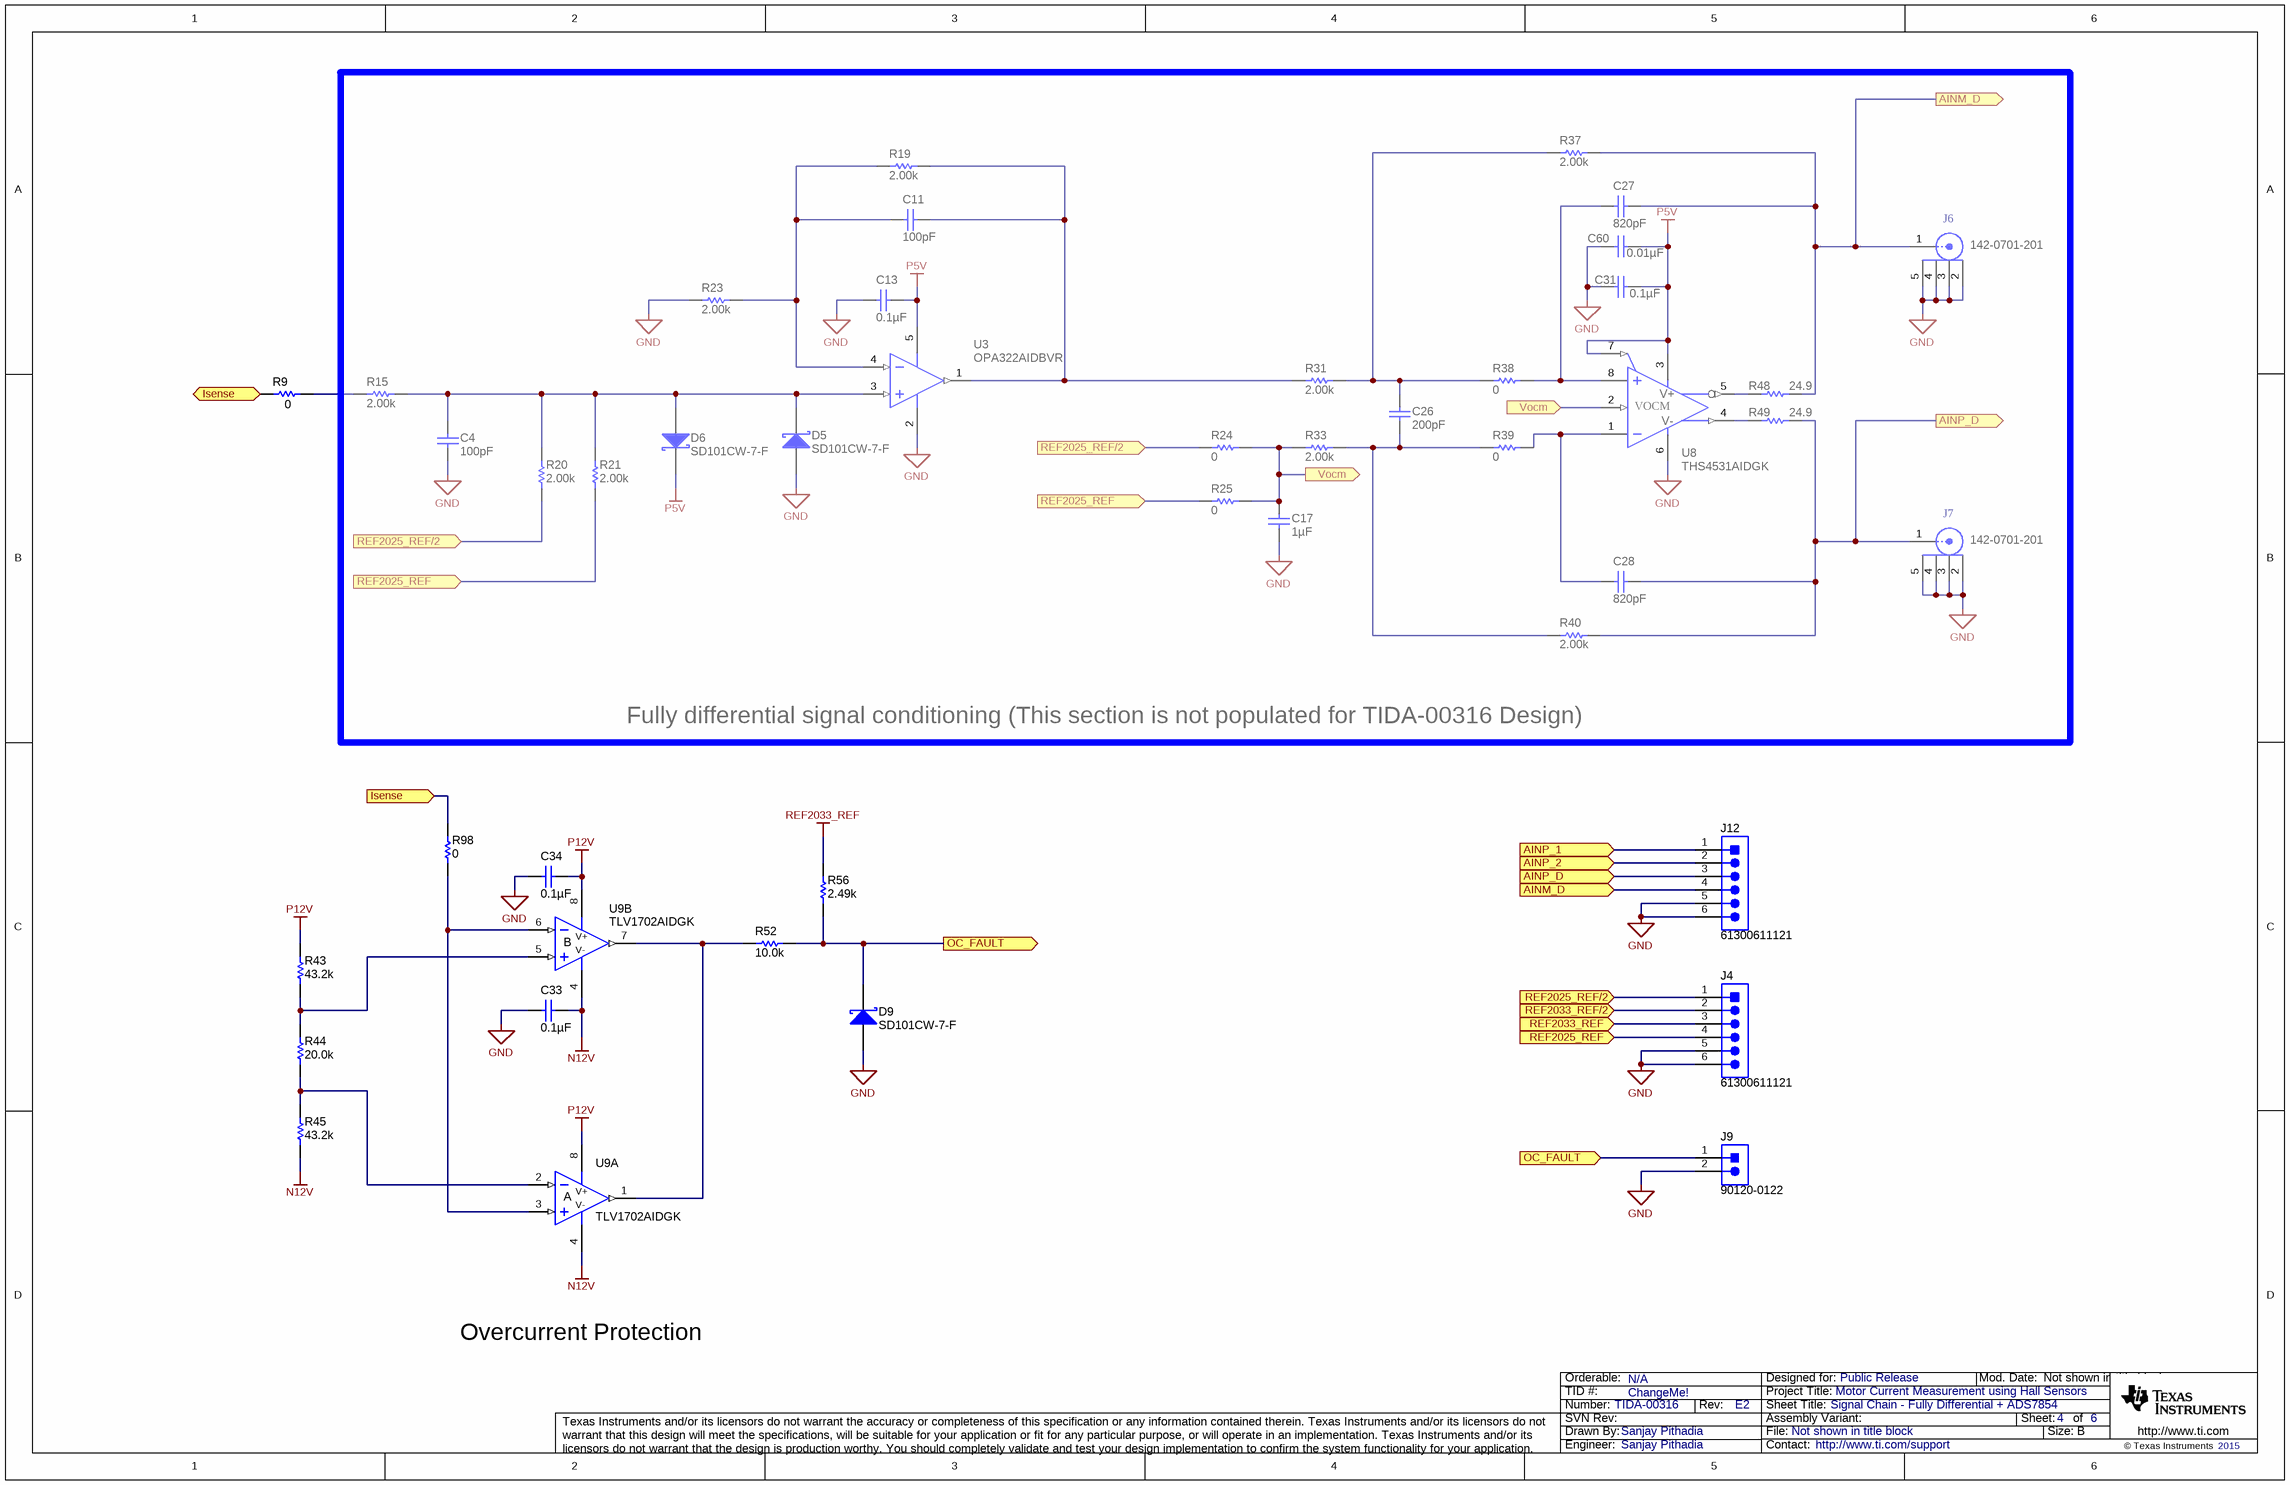
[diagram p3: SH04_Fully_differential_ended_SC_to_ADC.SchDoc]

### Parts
C4  ValueDisplayed: 100pF  [0603]  (hidden comment: C1608C0G2A101J)
C11  ValueDisplayed: 100pF  [0603]  (hidden comment: C1608C0G2A101J)
C13  ValueDisplayed: 0.1µF  [0603]  (hidden comment: GRM188R71H104KA93D)
C17  ValueDisplayed: 1µF  [0805_HV]  (hidden comment: C0805C105K8RACTU)
C26  ValueDisplayed: 200pF  [0603]  (hidden comment: GRM1885C2A201JA01D)
C27  ValueDisplayed: 820pF  [0603]  (hidden comment: C1608C0G1H821J)
C28  ValueDisplayed: 820pF  [0603]  (hidden comment: C1608C0G1H821J)
C31  ValueDisplayed: 0.1µF  [0603]  (hidden comment: GRM188R71H104KA93D)
C33  ValueDisplayed: 0.1µF  [0603]  (hidden comment: GRM188R71H104KA93D)
C34  ValueDisplayed: 0.1µF  [0603]  (hidden comment: GRM188R71H104KA93D)
C60  ValueDisplayed: 0.01µF  [0402]  (hidden comment: C0402C103J5RACTU)
D5  SD101CW-7-F  [SOD-123]
D6  SD101CW-7-F  [SOD-123]
D9  SD101CW-7-F  [SOD-123]
J4  61300611121  [WURTH_61300611121]
J6  142-0701-201  [Johnson_142-0701-20x]
J7  142-0701-201  [Johnson_142-0701-20x]
J9  90120-0122  [CONN_90120-0122]
J12  61300611121  [WURTH_61300611121]
R9  value 0  [0603]  (hidden comment: CRCW06030000Z0EA)
R15  ValueDisplayed: 2.00k  [0603]  (hidden comment: RC0603FR-072KL)
R19  ValueDisplayed: 2.00k  [0603]  (hidden comment: RC0603FR-072KL)
R20  ValueDisplayed: 2.00k  [0603]  (hidden comment: RC0603FR-072KL)
R21  ValueDisplayed: 2.00k  [0603]  (hidden comment: RC0603FR-072KL)
R23  ValueDisplayed: 2.00k  [0603]  (hidden comment: RC0603FR-072KL)
R24  value 0  [0603]  (hidden comment: CRCW06030000Z0EA)
R25  value 0  [0603]  (hidden comment: CRCW06030000Z0EA)
R31  ValueDisplayed: 2.00k  [0603]  (hidden comment: RG1608P-202-B-T5)
R33  ValueDisplayed: 2.00k  [0603]  (hidden comment: RG1608P-202-B-T5)
R37  ValueDisplayed: 2.00k  [0603]  (hidden comment: RG1608P-202-B-T5)
R38  value 0  [0603]  (hidden comment: CRCW06030000Z0EA)
R39  value 0  [0603]  (hidden comment: CRCW06030000Z0EA)
R40  ValueDisplayed: 2.00k  [0603]  (hidden comment: RG1608P-202-B-T5)
R43  ValueDisplayed: 43.2k  [0603]  (hidden comment: CRCW060343K2FKEA)
R44  ValueDisplayed: 20.0k  [0603]  (hidden comment: RC0603FR-0720KL)
R45  ValueDisplayed: 43.2k  [0603]  (hidden comment: CRCW060343K2FKEA)
R48  ValueDisplayed: 24.9  [0603]  (hidden comment: CRCW060324R9FKEA)
R49  ValueDisplayed: 24.9  [0603]  (hidden comment: CRCW060324R9FKEA)
R52  ValueDisplayed: 10.0k  [0603]  (hidden comment: CRCW060310K0FKEA)
R56  ValueDisplayed: 2.49k  [0603]  (hidden comment: CRCW06032K49FKEA)
R98  value 0  [0603]  (hidden comment: CRCW06030000Z0EA)
U3  OPA322AIDBVR  [DBV0005A_N]
U8  THS4531AIDGK  [DGK0008A_N]
U9  TLV1702AIDGK  [DGK0008A_N]  (parts A,B of 2)

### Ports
AINM_D (in), AINM_D (out), AINP_1 (in), AINP_2 (in), AINP_D (in), AINP_D (out), Isense (in), OC_FAULT (in), OC_FAULT (out), REF2025_REF (in), REF2025_REF/2 (in), REF2033_REF (in), REF2033_REF/2 (in), Vocm (in), Vocm (out)

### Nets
GND: C4.2 C13.2 C17.2 C31.2 C33.2 C34.2 C60.2 D5.2(A) D9.2(A) J4.5 J4.6 J6.2 J6.3 J6.4 J6.5 J7.2 J7.3 J7.4 J7.5 J9.2 J12.5 J12.6 R23.1 U3.2(V-) U8.6(VS-)
N12V: C33.1 R45.1 U9.4(V-)
P5V: C13.1 C31.1 C60.1 D6.1(K) U3.5(V+) U8.3(VS+) U8.7(~{PD})
P12V: C34.1 R43.2 U9.8(V+)
REF2033_REF: R56.2
AINM_D: C27.1 J6.1 J12.4 R37.2 R48.1 ; port AINM_D
AINP_1: J12.1 ; port AINP_1
AINP_2: J12.2 ; port AINP_2
AINP_D: C28.1 J7.1 J12.3 R40.2 R49.1 ; port AINP_D
Isense: R9.2 R98.1 ; port Isense
OC_FAULT: D9.1(K) J9.1 R52.2 R56.1 ; port OC_FAULT
REF2025_REF: J4.4 R21.1 R25.2 ; port REF2025_REF
REF2025_REF/2: J4.1 R20.1 R24.2 ; port REF2025_REF/2
REF2033_REF: J4.3 ; port REF2033_REF  [a separate net that carries the same name]
REF2033_REF/2: J4.2 ; port REF2033_REF/2
Vocm: C17.1 R24.1 R25.1 R33.1 U8.2(VOCM) ; port Vocm
NetC4_1: C4.1 D5.1(K) D6.2(A) R15.2 R20.2 R21.2 U3.3(IN+)
NetC11_1: C11.1 R19.1 R31.1 U3.1(OUT)
NetC11_2: C11.2 R19.2 R23.2 U3.4(IN-)
NetC26_1: C26.1 R31.2 R37.1 R38.2
NetC26_2: C26.2 R33.2 R39.2 R40.1
NetC27_2: C27.2 R38.1 U8.8(VIN+)
NetC28_2: C28.2 R39.1 U8.1(VIN-)
NetR9_1: R9.1 R15.1
NetR43_1: R43.1 R44.2 U9.5(IN+)
NetR44_1: R44.1 R45.2 U9.2(IN-)
NetR48_2: R48.2 U8.5(VOUT-)
NetR49_2: R49.2 U8.4(VOUT+)
NetR52_1: R52.1 U9.1(OUT) U9.7(OUT)
NetR98_2: R98.2 U9.3(IN+) U9.6(IN-)

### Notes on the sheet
- Fully differential signal conditioning (This section is not populated for TIDA-00316 Design)
- Overcurrent Protection

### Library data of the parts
C4 C11 = C1608C0G2A101J: as C3 on sheet SH03_Single_ended_SC_to_ADC
C13 C31 C33 C34 = GRM188R71H104KA93D: as C30 on sheet SH02_Power_supply
C17 = C0805C105K8RACTU: as C24 on sheet SH02_Power_supply
C26 = GRM1885C2A201JA01D: as C57 on sheet SH03_Single_ended_SC_to_ADC
C27 C28 = C1608C0G1H821J: CAP, CERM, 820 pF, 50 V, +/- 5%, C0G/NP0, 0603; Manufacturer: TDK; Polarized: N; CompType: Capacitor; Value: 820pF; U/M: EA; Cap_F: 0.00000000082; Tolerance_%: 5; ESR_ohm: 0.0482; Value1: 0.0482 ohm; VDC_V: 50; Value2: 50V; TaMin_C: -55; TaMax_C: 125
C60 = C0402C103J5RACTU: CAP, CERM, 0.01 µF, 50 V, +/- 5%, X7R, 0402; Manufacturer: Kemet; Polarized: N; CompType: Capacitor; Value: 0.01uF; U/M: EA; Cap_F: 0.00000001; Tolerance_%: 5; Value1: Unknown; VDC_V: 50; Value2: 50V; TaMin_C: -55; TaMax_C: 125
D5 D6 D9 = SD101CW-7-F: as D1 on sheet SH03_Single_ended_SC_to_ADC
J4 J12 = 61300611121: Header, 2.54 mm, 6x1, Gold, TH; Manufacturer: Wurth Elektronik; SymbolCreator: a0412235; U/M: EA
J6 J7 = 142-0701-201: as J5 on sheet SH03_Single_ended_SC_to_ADC
J9 = 90120-0122: Header, 100mil, 2x1, Tin, TH; Manufacturer: Molex; SymbolCreator: a0412235; U/M: EA
R9 R24 R25 R38 R39 R98 = CRCW06030000Z0EA: as R46 on sheet SH02_Power_supply
R15 R19-R21 R23 = RC0603FR-072KL: as R10 on sheet SH03_Single_ended_SC_to_ADC
R31 R33 R37 R40 = RG1608P-202-B-T5: RES, 2.00 k, 0.1%, 0.1 W, 0603; Manufacturer: Susumu Co Ltd; CompType: Resistor; Value: 2.00k; Res_ohm: 2000; Value_Code: 2k00; Tolerance_%: 0.1; Value2: 0.1W; VDC_V: 75; TempCo: 25 ppm/C; EIA_Code: E192; U/M: EA
R43 R45 = CRCW060343K2FKEA: RES, 43.2 k, 1%, 0.1 W, 0603; Manufacturer: Vishay-Dale; CompType: Resistor; Value: 43.2k; Res_ohm: 43200; Value_Code: 43k2; Tolerance_%: 1; Power_W: 0.1; Value2: 0.1W; VDC_V: 75; TempCo: 100 ppm/C; EIA_Code: E96; U/M: EA
R44 = RC0603FR-0720KL: RES, 20.0 k, 1%, 0.1 W, 0603; Manufacturer: Yageo America; CompType: Resistor; Value: 20.0k; Res_ohm: 20000; Value_Code: 20k0; Tolerance_%: 1; Power_W: 0.1; Value2: 0.1W; VDC_V: 150; TempCo: 200 ppm/C; EIA_Code: E96; U/M: EA
R48 R49 = CRCW060324R9FKEA: RES, 24.9, 1%, 0.1 W, 0603; Manufacturer: Vishay-Dale; CompType: Resistor; Value: 24.9; Value_Code: 24R9; Tolerance_%: 1; Power_W: 0.1; Value2: 0.1W; VDC_V: 75; TempCo: 100 ppm/C; EIA_Code: E96; U/M: EA
R52 = CRCW060310K0FKEA: RES, 10.0 k, 1%, 0.1 W, 0603; Manufacturer: Vishay-Dale; CompType: Resistor; Value: 10.0k; Res_ohm: 10000; Value_Code: 10k0; Tolerance_%: 1; Power_W: 0.1; Value2: 0.1W; VDC_V: 75; TempCo: 100 ppm/C; EIA_Code: E96; U/M: EA
R56 = CRCW06032K49FKEA: RES, 2.49 k, 1%, 0.1 W, 0603; Manufacturer: Vishay-Dale; CompType: Resistor; Value: 2.49k; Res_ohm: 2490; Value_Code: 2k49; Tolerance_%: 1; Power_W: 0.1; Value2: 0.1W; VDC_V: 75; TempCo: 100 ppm/C; EIA_Code: E96; U/M: EA
U3 = OPA322AIDBVR: 20 MHz, Low Noise, RRIO, CMOS Operational Amplifier with Shutdown, 1.8 to 5.5 V, -40 to 125 degC, 5-pin SOT23 (DBV0005A), Green (RoHS & no Sb/Br); Manufacturer: Texas Instruments; Alternate Manufacturer: None; Alternate PartNumber: Equivalent; CMRR(Min)(dB): 90; GBW(Typ)(MHz): 20; IIB(Max)(pA): 10; Iq per channel(Max)(mA): 1.9; Number of Channels: 1; Offset Drift(Typ)(uV/C): 1.8; Packing: LARGE T&R; Rating: Catalog; Sub Family: High Output Current Amplifier (>=50mA), Low Input Bias Current Amp (<=10pA), Low Noise Amp (<=10nV/rtHz), Low Supply Voltage Amplifier (<=2.7V), Precision Amplifier; Total Supply Voltage(Max)(+5V is 5, +/-5V is 10): 5.5; Vio (25C)(Max)(mV): 2
U8 = THS4531AIDGK: Ultra Low Power, Rail-to-Rail Output, Fully-Differential Amplifier, DGK0008A; Manufacturer: Texas Instruments; SymbolCreator: Altium; CompType: IC; U/M: EA
U9 = TLV1702AIDGK: 2.2-V to 36-V, microPower Comparator, DGK0008A; Manufacturer: Texas Instruments; CompType: IC; U/M: EA

## Sheet SH05_180_pin_connector_interface.SchDoc: Delfino Controller Interface
size 431 x 279 mm; Date: Not shown in title block; ApprovedBy: Not shown in title block; CheckedBy: Not shown in title block; Author: Not shown in title block; CompanyName: Not shown in title block; DrawnBy: Sanjay Pithadia; Engineer: Sanjay Pithadia; Organization: Not shown in title block; Address1: Not shown in title block; Address2: Not shown in title block; Address3: Not shown in title block; Address4: Not shown in title block; DocumentNumber: 6; Revision: Use project parameter SCH_Rev; SheetNumber: 5; SheetTotal: 6; PageSetup: Record=PageOptions|CenterHorizontal=True|CenterVertical=True|PrintScale=1.00|XCorrection=1.00|YCorrection=1.00|PrintKind=0|BorderSize=5000000|LeftOffset=0|BottomOffset=0|Orientation=2|PaperLength=1000|PaperWidth=1000|Scale=100|PaperSource=15|PrintQuality=600|MediaType=1|DitherType=10|PaperKind=Letter|PrintScaleMode=1
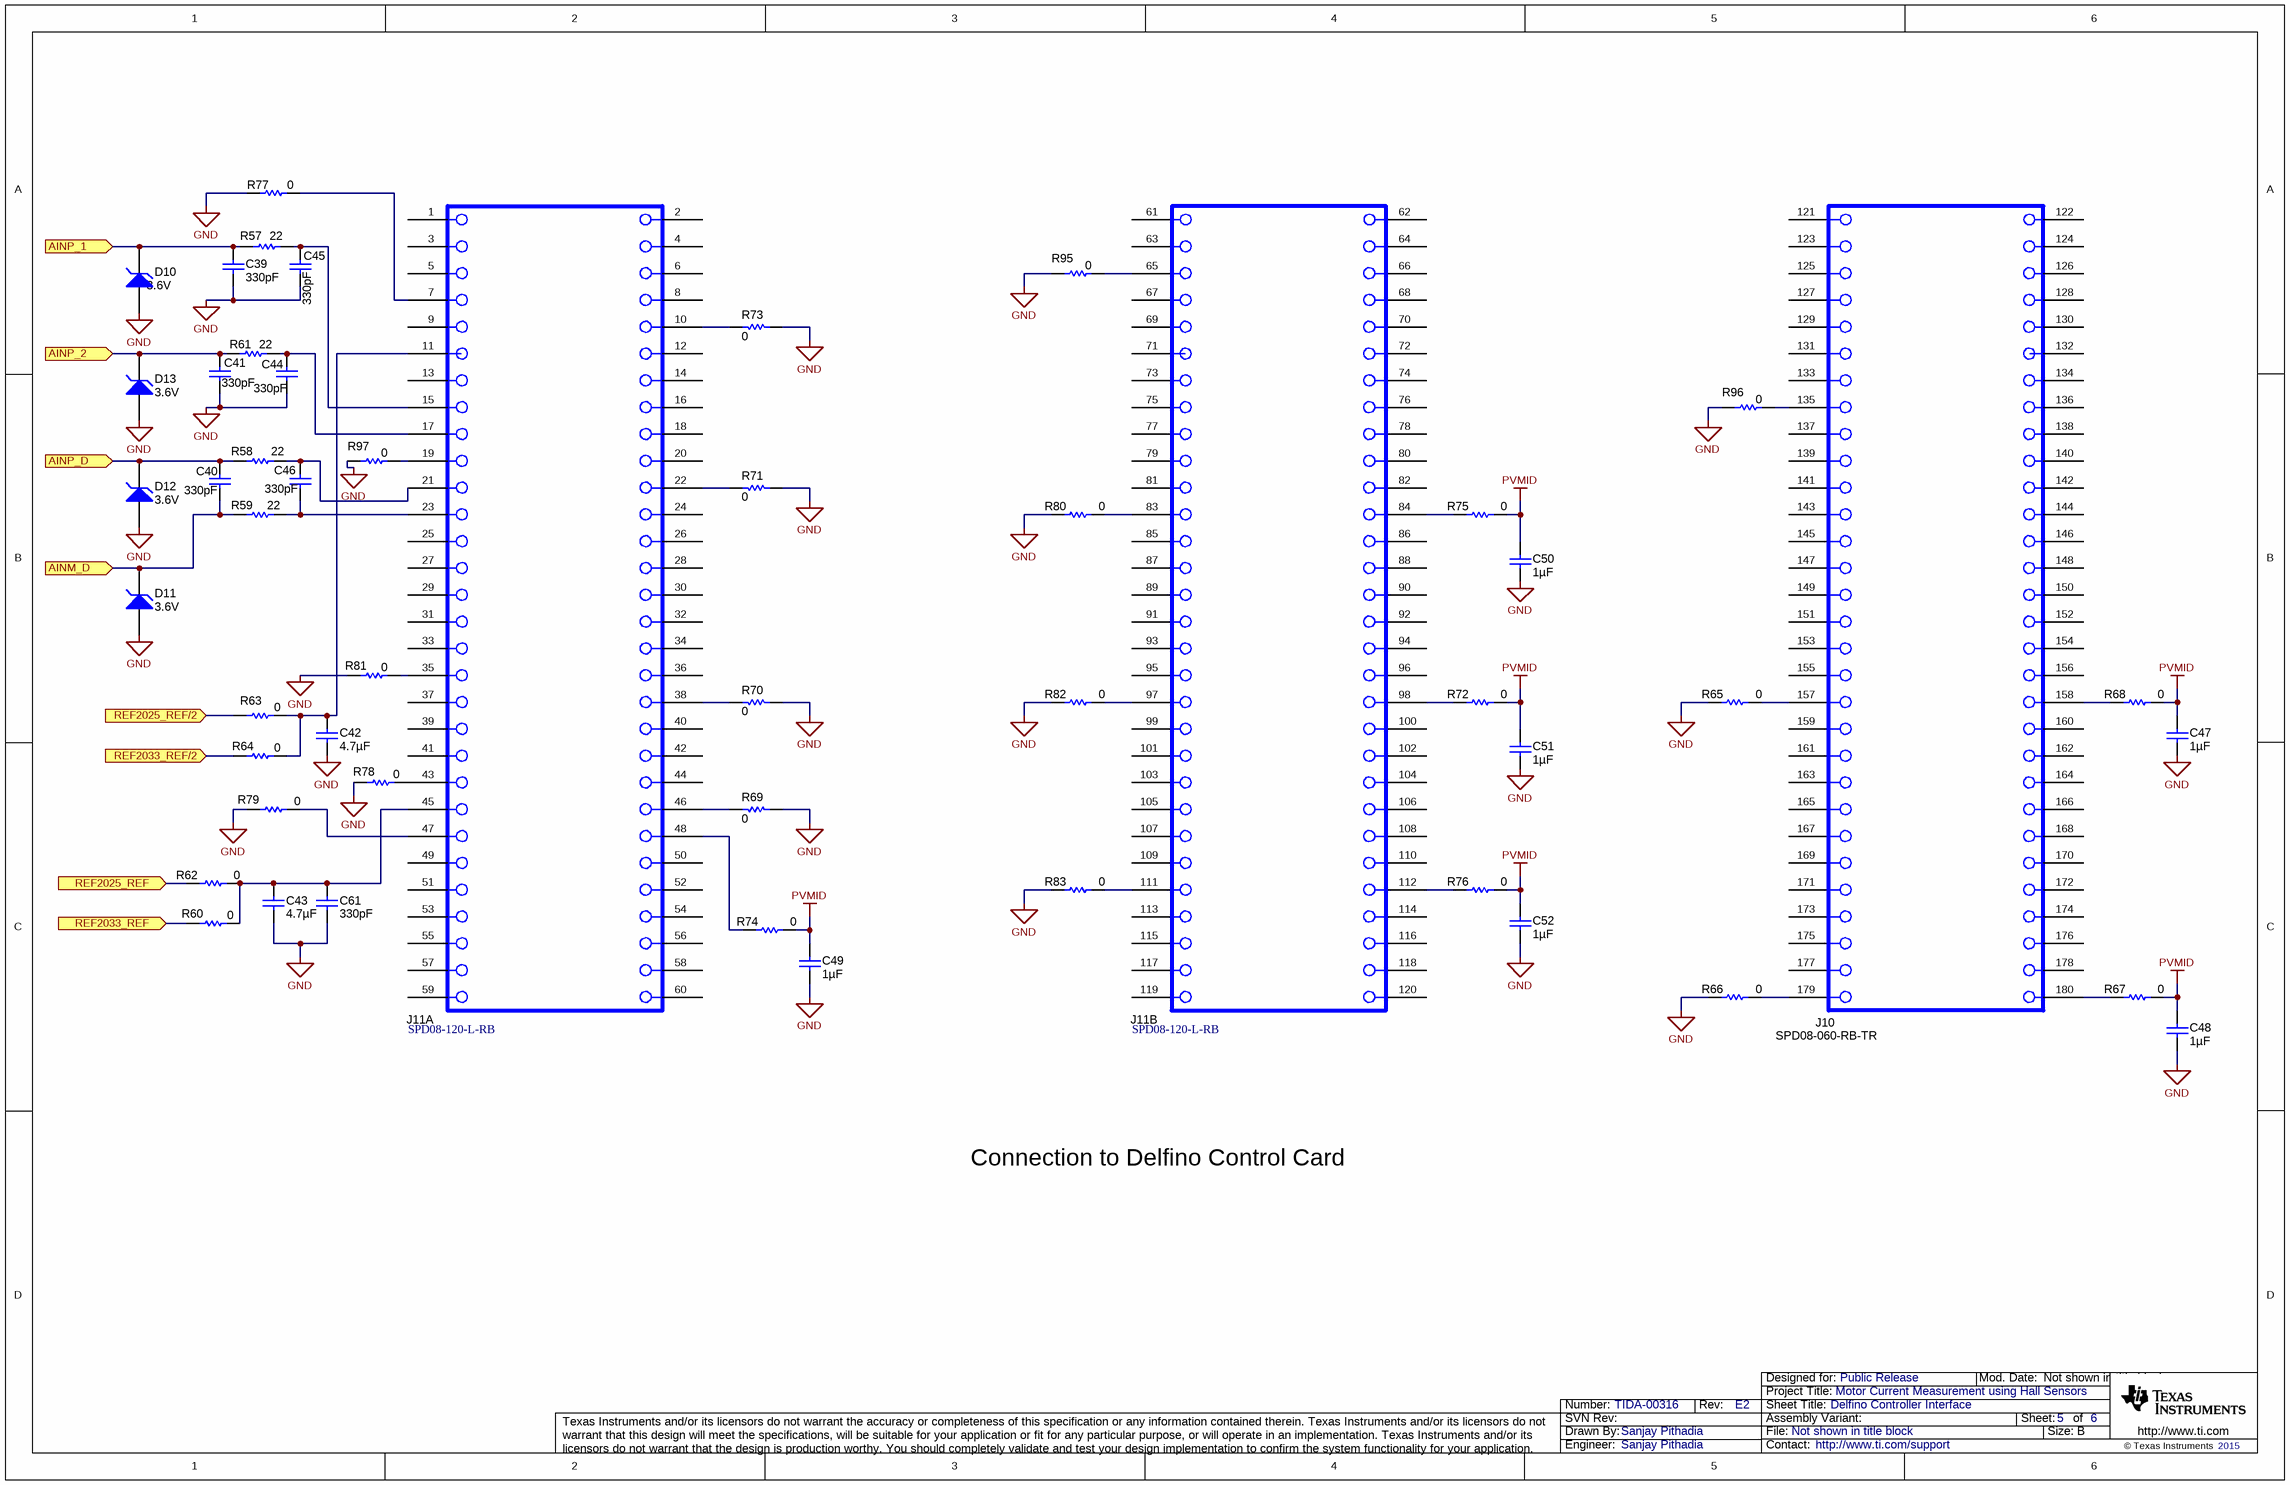
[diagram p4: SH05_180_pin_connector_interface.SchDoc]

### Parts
C39  ValueDisplayed: 330pF  [0603]  (hidden comment: C1608C0G1H331F080AA)
C40  ValueDisplayed: 330pF  [0603]  (hidden comment: C1608C0G1H331F080AA)
C41  ValueDisplayed: 330pF  [0603]  (hidden comment: C1608C0G1H331F080AA)
C42  ValueDisplayed: 4.7µF  [0603]  (hidden comment: 0603ZD475KAT2A)
C43  ValueDisplayed: 4.7µF  [0603]  (hidden comment: 0603ZD475KAT2A)
C44  ValueDisplayed: 330pF  [0603]  (hidden comment: C1608C0G1H331F080AA)
C45  ValueDisplayed: 330pF  [0603]  (hidden comment: C1608C0G1H331F080AA)
C46  ValueDisplayed: 330pF  [0603]  (hidden comment: C1608C0G1H331F080AA)
C47  ValueDisplayed: 1µF  [0805_HV]  (hidden comment: C0805C105K8RACTU)
C48  ValueDisplayed: 1µF  [0805_HV]  (hidden comment: C0805C105K8RACTU)
C49  ValueDisplayed: 1µF  [0805_HV]  (hidden comment: C0805C105K8RACTU)
C50  ValueDisplayed: 1µF  [0805_HV]  (hidden comment: C0805C105K8RACTU)
C51  ValueDisplayed: 1µF  [0805_HV]  (hidden comment: C0805C105K8RACTU)
C52  ValueDisplayed: 1µF  [0805_HV]  (hidden comment: C0805C105K8RACTU)
C61  ValueDisplayed: 330pF  [0603]  (hidden comment: C1608C0G1H331F080AA)
D10  value 3.6V  [SOD-123]  (hidden comment: MMSZ5227B-7-F)
D11  value 3.6V  [SOD-123]  (hidden comment: MMSZ5227B-7-F)
D12  value 3.6V  [SOD-123]  (hidden comment: MMSZ5227B-7-F)
D13  value 3.6V  [SOD-123]  (hidden comment: MMSZ5227B-7-F)
J10  SPD08-060-RB-TR  [HSEC8-130-01-L-DV-A]
J11  SPD08-120-L-RB  [HSEC8-160-01-L-DV-A-L]  (parts A,B of 2)
R57  ValueDisplayed: 22  [0603]  (hidden comment: CRCW060322R0JNEA)
R58  ValueDisplayed: 22  [0603]  (hidden comment: CRCW060322R0JNEA)
R59  ValueDisplayed: 22  [0603]  (hidden comment: CRCW060322R0JNEA)
R60  value 0  [0603]  (hidden comment: CRCW06030000Z0EA)
R61  ValueDisplayed: 22  [0603]  (hidden comment: CRCW060322R0JNEA)
R62  value 0  [0603]  (hidden comment: CRCW06030000Z0EA)
R63  value 0  [0603]  (hidden comment: CRCW06030000Z0EA)
R64  value 0  [0603]  (hidden comment: CRCW06030000Z0EA)
R65  value 0  [0603]  (hidden comment: CRCW06030000Z0EA)
R66  value 0  [0603]  (hidden comment: CRCW06030000Z0EA)
R67  value 0  [0603]  (hidden comment: CRCW06030000Z0EA)
R68  value 0  [0603]  (hidden comment: CRCW06030000Z0EA)
R69  value 0  [0603]  (hidden comment: CRCW06030000Z0EA)
R70  value 0  [0603]  (hidden comment: CRCW06030000Z0EA)
R71  value 0  [0603]  (hidden comment: CRCW06030000Z0EA)
R72  value 0  [0603]  (hidden comment: CRCW06030000Z0EA)
R73  value 0  [0603]  (hidden comment: CRCW06030000Z0EA)
R74  value 0  [0603]  (hidden comment: CRCW06030000Z0EA)
R75  value 0  [0603]  (hidden comment: CRCW06030000Z0EA)
R76  value 0  [0603]  (hidden comment: CRCW06030000Z0EA)
R77  value 0  [0603]  (hidden comment: CRCW06030000Z0EA)
R78  value 0  [0603]  (hidden comment: CRCW06030000Z0EA)
R79  value 0  [0603]  (hidden comment: CRCW06030000Z0EA)
R80  value 0  [0603]  (hidden comment: CRCW06030000Z0EA)
R81  value 0  [0603]  (hidden comment: CRCW06030000Z0EA)
R82  value 0  [0603]  (hidden comment: CRCW06030000Z0EA)
R83  value 0  [0603]  (hidden comment: CRCW06030000Z0EA)
R95  value 0  [0603]  (hidden comment: CRCW06030000Z0EA)
R96  value 0  [0603]  (hidden comment: CRCW06030000Z0EA)
R97  value 0  [0603]  (hidden comment: CRCW06030000Z0EA)

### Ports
AINM_D (in), AINP_1 (in), AINP_2 (in), AINP_D (in), REF2025_REF (in), REF2025_REF/2 (in), REF2033_REF (in), REF2033_REF/2 (in)

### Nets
GND: C39.2 C41.2 C42.2 C43.2 C44.2 C45.2 C47.2 C48.2 C49.2 C50.2 C51.2 C52.2 C61.2 D10.2(A) D11.2(A) D12.2(A) D13.2(A) R65.1 R66.1 R69.1 R70.1 R71.1 R73.1 R77.2 R78.1 R79.1 R80.1 R81.1 R82.1 R83.1 R95.1 R96.1 R97.1
PVMID: C47.1 C48.1 C49.1 C50.1 C51.1 C52.1 R67.2 R68.2 R72.2 R74.2 R75.2 R76.2
AINM_D: C40.2 D11.1(K) R59.1 ; port AINM_D
AINP_1: C39.1 D10.1(K) R57.1 ; port AINP_1
AINP_2: C41.1 D13.1(K) R61.1 ; port AINP_2
AINP_D: C40.1 D12.1(K) R58.1 ; port AINP_D
REF2025_REF: R62.1 ; port REF2025_REF
REF2025_REF/2: R63.1 ; port REF2025_REF/2
REF2033_REF: R60.1 ; port REF2033_REF
REF2033_REF/2: R64.1 ; port REF2033_REF/2
NetC42_1: C42.1 J11.11 R63.2 R64.2
NetC43_1: C43.1 C61.1 J11.45 R60.2 R62.2
NetC44_1: C44.1 J11.17 R61.2
NetC45_1: C45.1 J11.15 R57.2
NetC46_1: C46.1 J11.21 R58.2
NetC46_2: C46.2 J11.23 R59.2
NetJ10_135: J10.135 R96.2
NetJ10_157: J10.157 R65.2
NetJ10_158: J10.158 R68.1
NetJ10_179: J10.179 R66.2
NetJ10_180: J10.180 R67.1
NetJ11_7: J11.7 R77.1
NetJ11_10: J11.10 R73.2
NetJ11_19: J11.19 R97.2
NetJ11_22: J11.22 R71.2
NetJ11_35: J11.35 R81.2
NetJ11_38: J11.38 R70.2
NetJ11_43: J11.43 R78.2
NetJ11_46: J11.46 R69.2
NetJ11_47: J11.47 R79.2
NetJ11_48: J11.48 R74.1
NetJ11_65: J11.65 R95.2
NetJ11_83: J11.83 R80.2
NetJ11_84: J11.84 R75.1
NetJ11_97: J11.97 R82.2
NetJ11_98: J11.98 R72.1
NetJ11_111: J11.111 R83.2
NetJ11_112: J11.112 R76.1

Not connected (* = marked no-connect by the designer): J10 121 122 123 124 125 126 127 128 129 130 131 132 133 134 136 137 138 139 140 141 142 143 144 145 146 147 148 149 150 151 152 153 154 155 156 159 160 161 162 163 164 165 166 167 168 169 170 171 172 173 174 175 176 177 178; J11 1 2 3 4 5 6 8 9 12 13 14 16 18 20 24 25 26 27 28 29 30 31 32 33 34 36 37 39 40 41 42 44 49 50 51 52 53 54 55 56 57 58 59 60 61 62 63 64 66 67 68 69 70 71 72 73 74 75 76 77 78 79 80 81 82 85 86 87 88 89 90 91 92 93 94 95 96 99 100 101 102 103 104 105 106 107 108 109 110 113 114 115 116 117 118 119 120

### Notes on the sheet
- Connection to Delfino Control Card

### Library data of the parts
C39-C41 C44-C46 C61 = C1608C0G1H331F080AA: CAP, CERM, 330 pF, 50 V, +/- 1%, C0G/NP0, 0603; Manufacturer: TDK; Polarized: N; CompType: Capacitor; Value: 330pF; U/M: EA; Cap_F: 0.00000000033; Tolerance_%: 1; Value1: Unknown; VDC_V: 50; Value2: 50V; TaMin_C: -55; TaMax_C: 125
C42 C43 = 0603ZD475KAT2A: CAP, CERM, 4.7 µF, 10 V, +/- 10%, X5R, 0603; Manufacturer: AVX; Polarized: N; CompType: Capacitor; Value: 4.7uF; U/M: EA; Cap_F: 0.0000047; Tolerance_%: 10; Value1: Unknown; Value2: 10V; TaMin_C: -55; TaMax_C: 85
C47-C52 = C0805C105K8RACTU: as C24 on sheet SH02_Power_supply
D10-D13 = MMSZ5227B-7-F: Diode, Zener, 3.6V, 500mW, SOD-123; Manufacturer: Diodes Inc.; SymbolCreator: a0412235; U/M: EA; Power_W: 0.5; Vz_V: 3.6; Value1: 0.5W; RJA_CperW: 350
J10 = HSEC8-130-01-L-DV-A: CONN HIGH SPD CARD EDGE 60 POS; Manufacturer: 3M; SymbolCreator: x0120606; CompType: Edge Rate Card Socket
J11 = HSEC8-160-01-L-DV-A-L: CONN HIGH SPD CARD EDGE 120 POS; Manufacturer: 3M
R57-R59 R61 = CRCW060322R0JNEA: RES, 22, 5%, 0.1 W, 0603; Manufacturer: Vishay-Dale; CompType: Resistor; Value: 22; Value_Code: 22R0; Tolerance_%: 5; Power_W: 0.1; Value2: 0.1W; VDC_V: 75; TempCo: 200 ppm/C; EIA_Code: E24; U/M: EA
R60 R62-R83 R95-R97 = CRCW06030000Z0EA: as R46 on sheet SH02_Power_supply

## Sheet SH06_Hardware.SchDoc
size 431 x 279 mm; Date: Not shown in title block; ApprovedBy: Not shown in title block; CheckedBy: Not shown in title block; Author: Not shown in title block; CompanyName: Not shown in title block; Engineer: Not shown in title block; Organization: Not shown in title block; Address1: Not shown in title block; Address2: Not shown in title block; Address3: Not shown in title block; Address4: Not shown in title block; DocumentNumber: 1; Revision: Use project parameter SCH_Rev; SheetNumber: 6; SheetTotal: 6; PageSetup: Record=PageOptions|CenterHorizontal=True|CenterVertical=True|PrintScale=1.00|XCorrection=1.00|YCorrection=1.00|PrintKind=0|BorderSize=5000000|LeftOffset=0|BottomOffset=0|Orientation=2|PaperLength=1000|PaperWidth=1000|Scale=100|PaperSource=15|PrintQuality=600|MediaType=1|DitherType=10|PaperKind=Letter|PrintScaleMode=1
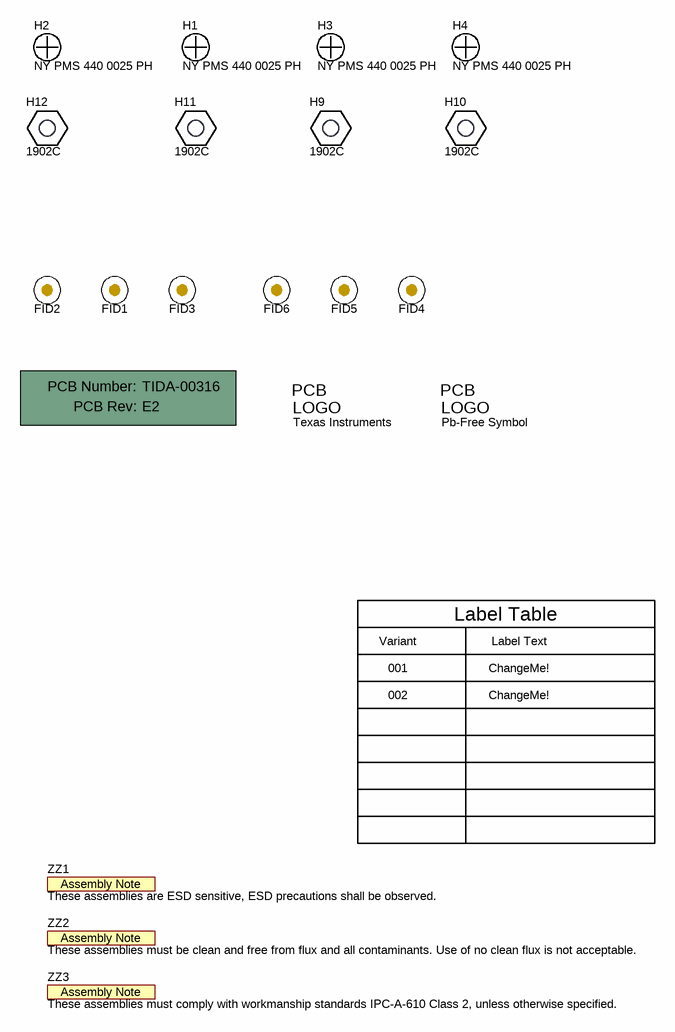
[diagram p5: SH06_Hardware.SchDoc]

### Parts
!PCB1  Printed Circuit Board  (value not drawn)  (mechanical)
FID1  Fiducial  [Fiducial10-20]  (value not drawn)
FID2  Fiducial  [Fiducial10-20]  (value not drawn)
FID3  Fiducial  [Fiducial10-20]  (value not drawn)
FID4  Fiducial  [Fiducial10-20]  (value not drawn)
FID5  Fiducial  [Fiducial10-20]  (value not drawn)
FID6  Fiducial  [Fiducial10-20]  (value not drawn)
H1  NY PMS 440 0025 PH  [NY PMS 440 0025 PH]
H2  NY PMS 440 0025 PH  [NY PMS 440 0025 PH]
H3  NY PMS 440 0025 PH  [NY PMS 440 0025 PH]
H4  NY PMS 440 0025 PH  [NY PMS 440 0025 PH]
H9  1902C  [Keystone_1902C]
H10  1902C  [Keystone_1902C]
H11  1902C  [Keystone_1902C]
H12  1902C  [Keystone_1902C]
Logo1  Texas Instruments  [TI_Stacked_Overlay_Medium]  (no BOM)
Logo2  Pb-Free Symbol  [Pb-Free_Overlay_Small]  (no BOM)
ZZ1  These assemblies are ESD sensitive, ESD precautions shall be observed.  [AssemblyNote]  (no BOM)
ZZ2  These assemblies must be clean and free from flux and all contaminants. Use of no clean flux is not acceptable.  [AssemblyNote]  (no BOM)
ZZ3  These assemblies must comply with workmanship standards IPC-A-610 Class 2, unless otherwise specified.  [AssemblyNote]  (no BOM)

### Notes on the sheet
- Variant
- Label Table
- Label Text
- 001
- 002
- ChangeMe!

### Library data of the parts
!PCB1 = PCB: Manufacturer: Any; PartNumber: TIDA-00316; SymbolCreator: a0412235
FID1-FID6 = Fiducial: Fiducial mark.  There is nothing to buy or mount.; SymbolCreator: codlsc
H1-H4 = NY PMS 440 0025 PH: Machine Screw, Round, #4-40 x 1/4, Nylon, Philips panhead; Manufacturer: B&F Fastener Supply; CompType: Hardware; SymbolCreator: codlsc; U/M: EA
H9-H12 = 1902C: Standoff, Hex, 0.5"L #4-40 Nylon; Manufacturer: Keystone; CompType: Hardware
Logo1 = TI_Logo: Texas Instrument Corporate Signature; SymbolCreator: a0412235
Logo2 = Pb-Free: SymbolCreator: a0412235
ZZ1-ZZ3 = AssemblyNote: SymbolCreator: codlsc

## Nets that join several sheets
GND: SH02_Power_supply (39 pins), SH03_Single_ended_SC_to_ADC (27 pins), SH04_Fully_differential_ended_SC_to_ADC (25 pins), SH05_180_pin_connector_interface (33 pins)
N12V: SH02_Power_supply (C15.1 C20.1 R30.2 U4.1), SH03_Single_ended_SC_to_ADC (5 pins), SH04_Fully_differential_ended_SC_to_ADC (C33.1 R45.1 U9.4)
P5V: SH02_Power_supply (10 pins), SH03_Single_ended_SC_to_ADC (C22.1 D2.1 D7.1 U7.8), SH04_Fully_differential_ended_SC_to_ADC (7 pins)
P12V: SH02_Power_supply (C16.1 C21.1 R32.2 U5.1), SH03_Single_ended_SC_to_ADC (5 pins), SH04_Fully_differential_ended_SC_to_ADC (C34.1 R43.2 U9.8)
PVMID: SH02_Power_supply (12 pins), SH05_180_pin_connector_interface (12 pins)
AINM_D: SH04_Fully_differential_ended_SC_to_ADC (5 pins), SH05_180_pin_connector_interface (C40.2 D11.1 R59.1)
AINP_1: SH03_Single_ended_SC_to_ADC (C57.1 J5.1 R41.1 U7.7), SH04_Fully_differential_ended_SC_to_ADC (J12.1), SH05_180_pin_connector_interface (C39.1 D10.1 R57.1)
AINP_2: SH03_Single_ended_SC_to_ADC (C19.1 J8.1 R34.2 U6.7), SH04_Fully_differential_ended_SC_to_ADC (J12.2), SH05_180_pin_connector_interface (C41.1 D13.1 R61.1)
AINP_D: SH04_Fully_differential_ended_SC_to_ADC (5 pins), SH05_180_pin_connector_interface (C40.1 D12.1 R58.1)
Isense: SH03_Single_ended_SC_to_ADC (5 pins), SH04_Fully_differential_ended_SC_to_ADC (R9.2 R98.1)
REF2025_REF: SH02_Power_supply (C30.1 R47.1), SH03_Single_ended_SC_to_ADC (R91.1 R92.2), SH04_Fully_differential_ended_SC_to_ADC (J4.4 R21.1 R25.2), SH05_180_pin_connector_interface (R62.1)
REF2025_REF/2: SH02_Power_supply (C35.1 R50.1), SH04_Fully_differential_ended_SC_to_ADC (J4.1 R20.1 R24.2), SH05_180_pin_connector_interface (R63.1)
REF2033_REF: SH02_Power_supply (C32.1 R46.1), SH04_Fully_differential_ended_SC_to_ADC (J4.3), SH05_180_pin_connector_interface (R60.1)
REF2033_REF/2: SH02_Power_supply (C37.1 R51.1), SH03_Single_ended_SC_to_ADC (R27.1 R36.2), SH04_Fully_differential_ended_SC_to_ADC (J4.2), SH05_180_pin_connector_interface (R64.1)

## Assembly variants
001: not fitted C39 C40 C41 FID1 FID2 FID3 FID4 FID5 FID6 R24 R54 R85 R86 R88 R89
